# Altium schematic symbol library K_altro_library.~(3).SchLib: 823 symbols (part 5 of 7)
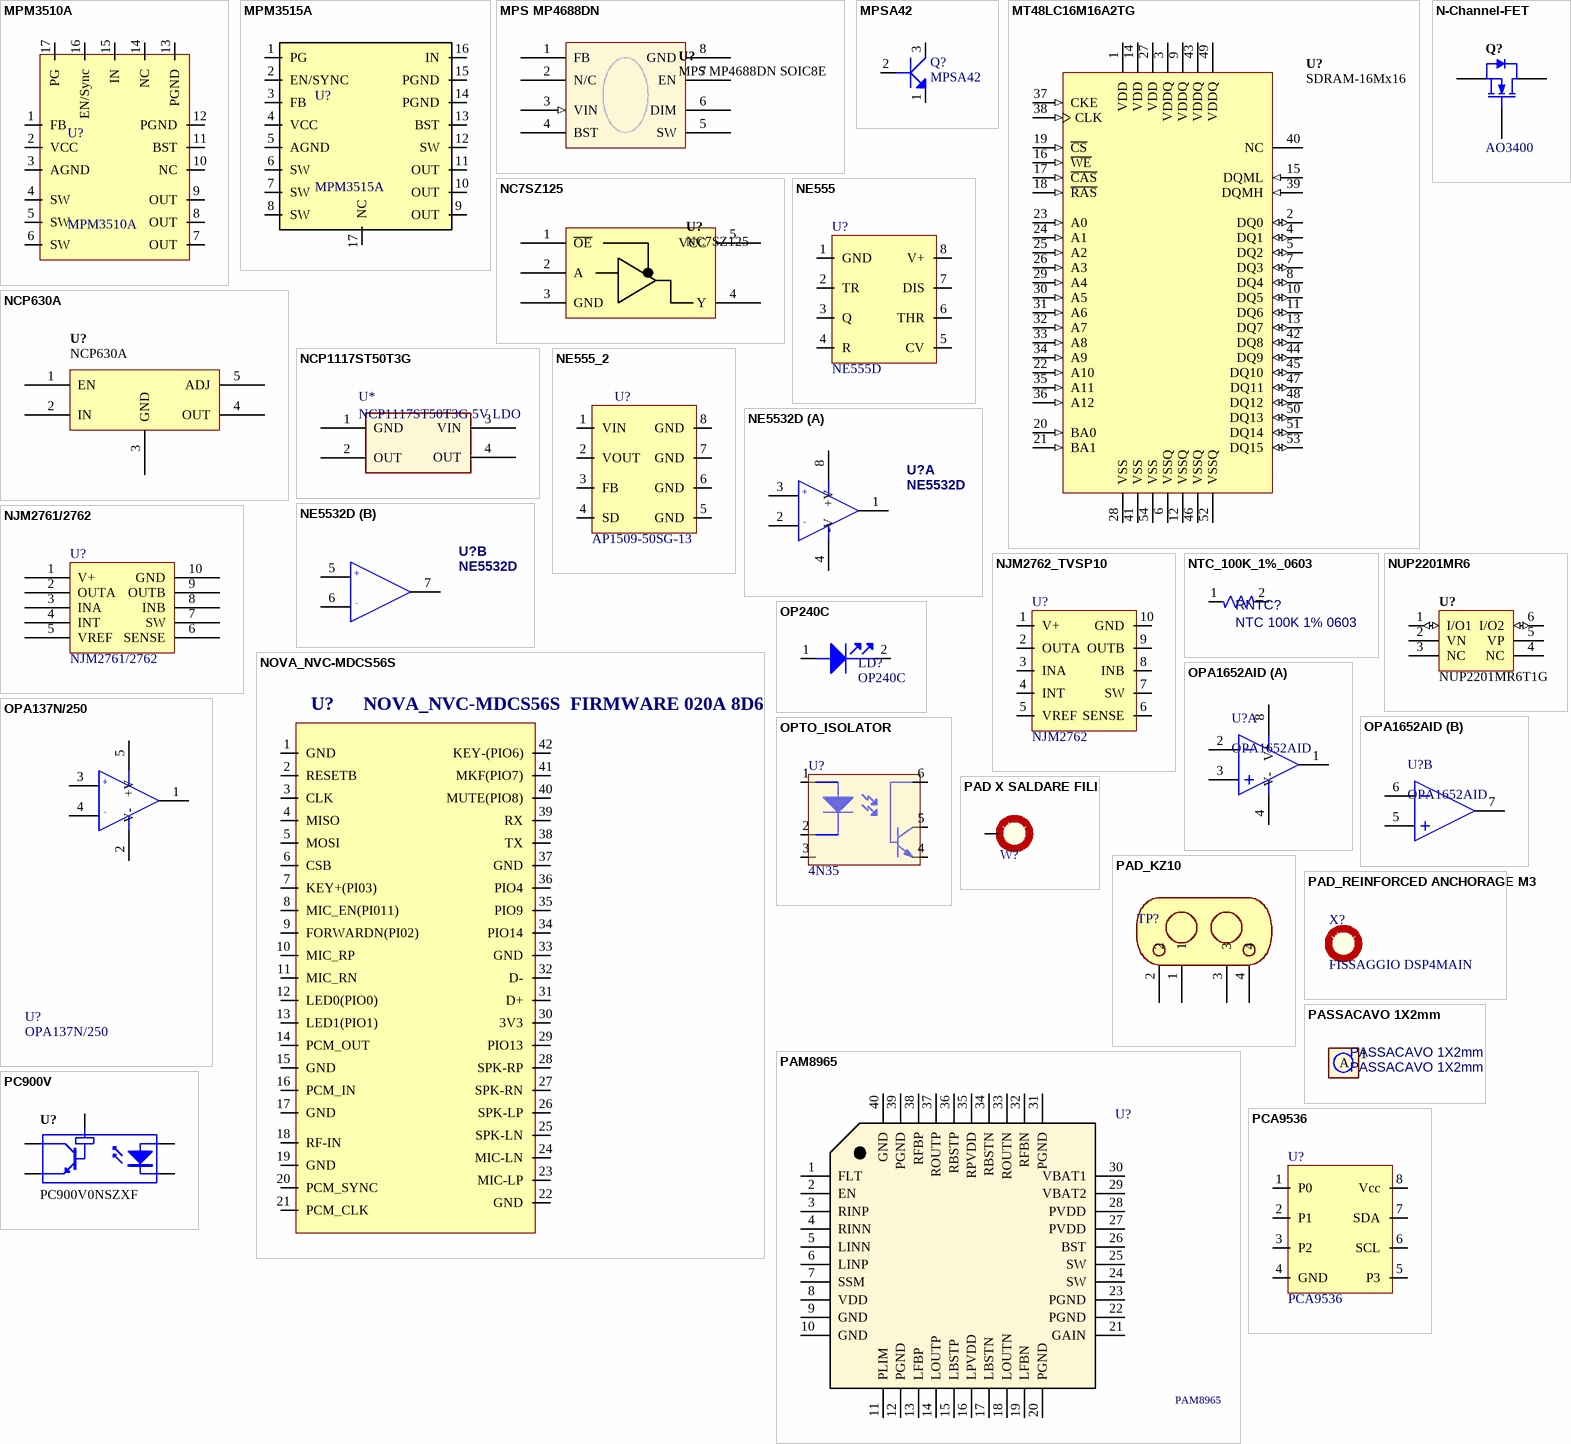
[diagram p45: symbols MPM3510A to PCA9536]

## N-Channel-FET
designator Q?, comment AO3400
N-channel Enhancement Mode Field-effect Transistor;  5.8A/30V; Aggiornato: NO; Costo: 0
footprint SOT95P230-3D
pins: 1 G, 2 D, 3 S

## NC7SZ125
designator U?
Aggiornato: SI; Costo: 0,087; Detail: (RS per >50pz); ContoLavoro: 0
footprint SOT-23 5PIN
pins: 1 ~{OE} "The NCP630 is active when a voltage greater than 2.0V is applied. The NCP630 will be placed into a shutdown mode when a voltage less than 0.8V is applied. If unused then connect the pin high.", 2 A, 3 GND, 4 Y, 5 VCC "Maintans 1.216V between itself and GND"

## NCP630A
designator U?
NCP630A, 3.0A Fast Linear Voltage Regulator, D2PAK; Max Input Voltage: 12 V; Max Output Current: 3 (6.0 peak) A; Max Output Voltage: mV; Aggiornato: NO; Costo: 0
footprint TO-263-2
pins: 1 EN "The NCP630 is active when a voltage greater than 2.0V is applied. The NCP630 will be placed into a shutdown mode when a voltage less than 0.8V is applied. If unused then connect the pin high.", 2 IN, 3 GND, 4 OUT, 5 ADJ "Maintans 1.216V between itself and GND"

## NCP1117ST50T3G
designator U*, comment NCP1117ST50T3G 5V LDO
Detail: prezzo RS; Costo: 0,30; Aggiornato: SI; ContoLavoro: 0
footprint SOT223
pins: 1 GND, 2 OUT, 3 VIN, 4 OUT

## NE555
designator U?, comment NE555D
Costo: 0,24; Aggiornato: NO; ContoLavoro: 0
footprint SO8
pins: 1 GND, 2 TR, 3 Q, 4 R, 5 CV, 6 THR, 7 DIS, 8 V+

## NE555_2
designator U?, comment AP1509-50SG-13
Costo: 1,57; Aggiornato: NO; ContoLavoro: 0
footprint SO8
pins: 1 VIN, 2 VOUT, 3 FB, 4 SD, 5 GND, 6 GND, 7 GND, 8 GND

## NE5532D
designator U?
NE5532D SMD DUAL OP AMP; Costo: 0,10; Aggiornato: SI; ContoLavoro: 0
footprint SO8
footprint SOIC150-8N
part A pins: 1 OUT, 2 -IN, 3 +IN, 4 -V, 8 +V
part B pins: 5 +IN, 6 -IN, 7 OUT

## NJM2761/2762
designator U?
Audio Limiter; Costo: 0; Aggiornato: NO
footprint NJM_TVSP10 (TSSOP, 10-Leads, Body 3x3mm, Pitch 0.5mm, IPC Medium Density)
pins: 1 V+, 2 OUTA, 3 INA, 4 INT, 5 VREF, 6 SENSE, 7 SW, 8 INB, 9 OUTB, 10 GND

## NJM2762_TVSP10
designator U?, comment NJM2762
Hpcode: ICNJM2762RB2; Costo: 0,52; Aggiornato: NO; ContoLavoro: 0
footprint TVSP10
pins: 1 V+, 2 OUTA, 3 INA, 4 INT, 5 VREF, 6 SENSE, 7 SW, 8 INB, 9 OUTB, 10 GND

## NOVA_NVC-MDCS56S
designator U?, comment NOVA_NVC-MDCS56S  FIRMWARE 020A 8D69
Aggiornato: NO; Costo: 0
footprint Bluetooth_NVC-MDCS56S
pins: 1 GND, 2 RESETB, 3 CLK, 4 MISO, 5 MOSI, 6 CSB, 7 KEY+(PI03), 8 MIC_EN(PI011), 9 FORWARDN(PI02), 10 MIC_RP, 11 MIC_RN, 12 LED0(PIO0), 13 LED1(PIO1), 14 PCM_OUT, 15 GND, 16 PCM_IN, 17 GND, 18 RF-IN, 19 GND, 20 PCM_SYNC, 21 PCM_CLK, 22 GND, 23 MIC-LP, 24 MIC-LN, 25 SPK-LN, 26 SPK-LP, 27 SPK-RN, 28 SPK-RP, 29 PIO13, 30 3V3, 31 D+, 32 D-, 33 GND, 34 PIO14, 35 PIO9, 36 PIO4, 37 GND, 38 TX, 39 RX, 40 MUTE(PIO8), 41 MKF(PIO7), 42 KEY-(PIO6)

## NTC_100K_1%_0603
designator RNTC?, comment NTC 100K 1% 0603
Detail: 0,232€ RS >100pz; Costo: 0,232; Aggiornato: S; ContoLavoro: 0
footprint 0603N_RES
pins: 1, 2

## NUP2201MR6
designator U?, comment NUP2201MR6T1G
NUP2201MR6, Low Capacitance Diode Array, USB Protection; Max Input Voltage: mV; Max Output Current: mA; Aggiornato: NO; Costo: 0
footprint TSOP95P275-6
pins: 1 I/O1 (io) "Input/Output 1", 2 VN (power), 3 NC, 4 NC, 5 VP (power), 6 I/O2 (io)

## OP240C
designator LD?
LED IR Optek OP240C; Aggiornato: si; Costo: 0,546; ContoLavoro: 0
footprint OP240C
pins: 1 ANODE, 2 CATHODE

## OPA137N/250
designator U?
Detail: 2,438€ RS >5pz; Aggiornato: s; Costo: 2,438; ContoLavoro: 1
footprint SOT-23 5PIN
pins: 1 OUT, 2 V-, 3 +IN, 4 -IN, 5 +V

## OPA1652AID
designator U?
Sound Plus Low Noise and Distortion, General-Purpose, FET-Input Audio Operational Amplifier, 4.5 to 36 V, -40 to 85 degC, 8-pin SOIC (D8), Green (RoHS & no Sb/Br); Costo: 0,80; ContoLavoro: 0
footprint SOIC150-8N
part A pins: 1 OUT A, 2 IN A-, 3 IN A+, 4 V- (power), 8 V+ (power)
part B pins: 5 IN B+, 6 IN B-, 7 OUT B

## OPTO_ISOLATOR
designator U?, comment 4N35
Aggiornato: NO; Costo: 0
footprint DIP6
pins: 1 ANODE, 2 CATHODE, 3, 4 EMITTER, 5 COLLECTOR, 6 BASE

## PAD X SALDARE FILI
designator W?  (value not drawn)
PAD ANCORAGGIO; Aggiornato: NO; Costo: 0
footprint PAD-DIAM3.05-DR2
footprint PAD-DIAM3.05-DR2
footprint PAD-DIAM2.54-DR1.5
footprint PAD-DIAM2.565-DR2
footprint SMDPAD-RECTANGLE-W3-L8
footprint SMDPAD-ROUND-W3-L7
footprint PAD-W4.1-DR2.4
footprint FIDUCIAL_MARKER-SCHUH (Piazzola per controllo automatico delle saldature SMD (SCHUH))
footprint SIP-1-ETTINGER-13_14_229
footprint PAD-DIAM2-DR1
footprint PAD-DIAM5-DR2.3
footprint PAD-DIAM5.6-DR2.6
footprint PAD-DIAM3-DR1.5
footprint FISS-DIAM6.5-DR3.2
footprint PAD-W3-L5.08-DR1.5
pins: 1

## PAD_KZ10
designator TP?  (no BOM)
Costo: 0; Aggiornato: NO
footprint PAD_KZ10
pins: 1, 2, 3, 4

## PAD_REINFORCED ANCHORAGE M3
designator X?, comment FISSAGGIO DSP4MAIN  (no BOM)
PAD ANCORAGGIO VITE M3; Aggiornato: NO; Costo: 0
footprint FISS-DIAM7.2-DR3.3
footprint FISS-DIAM6.86-DR3.175
footprint FISS-DIAM7.2-DR3.1
footprint FISS-DIAM5.3-DR2.5
footprint FISS-OCT-X6.782-Y6.02-DR3.175
footprint FISS-OCT-X6.782-Y6.02-DR3.5
footprint FISS-DIAM6.5-DR3.1
footprint FISS-DIAM6.83-DR4.7-TSVASM3 (Foro per vite con testa svasata con altezza dal c.s. (dopo fissaggio): 0.5mm)
footprint FISS-DIAM6.5-DR3.2
footprint SCREW_M3_ELECTRIC
pins: 1 (power) hidden to GND

## PAM8965
designator U?
12W STEREO CLASS-D AUDIO AMPLIFIER; MPN: ADAU1701JSTZ; HPcode: da codificare; Detail: 2,50€ Mouser; Costo: 2,50; Aggiornato: NO; ContoLavoro: 0
footprint QFN40_5050 (QFN40_5mmx5mm)
pins: 1 FLT, 2 EN, 3 RINP "Right IN+", 4 RINN "Right IN-", 5 LINN "Left IN-", 6 LINP "Left IN+", 7 SSM, 8 VDD, 9 GND, 10 GND, 11 PLIM, 12 PGND, 13 LFBP, 14 LOUTP "Left OUT+", 15 LBSTP, 16 LPVDD, 17 LBSTN, 18 LOUTN "Left OUT-", 19 LFBN, 20 PGND, 21 GAIN, 22 PGND, 23 PGND, 24 SW, 25 SW, 26 BST, 27 PVDD, 28 PVDD, 29 VBAT2, 30 VBAT1, 31 PGND, 32 RFBN, 33 ROUTN "Right OUT-", 34 RBSTN, 35 RPVDD, 36 RBSTP, 37 ROUTP "Right OUT+", 38 RFBP, 39 PGND, 40 GND

## PASSACAVO 1X2mm
designator PASSACAVO 1X2mm
Costo: 0; Aggiornato: S
footprint PASSACAVO 1X2mm (Footprint not found)
pins: 1 A

## PC900V
designator U?, comment PC900V0NSZXF
OPTOISOLATOR; SMD; Digital Output, Normal OFF  Operation; Aggiornato: NO; Costo: 0
footprint H11L1SR2VM
pins: 1 A "Anode", 2 K "Cathode", 4 Vo "Collector", 5 GND "Emitter", 6 Vcc "Collector"

## PCA9536
designator U?
PCA9536 I2C GPIO EXPANDER; Detail: Da quotare; Costo: 0,99; Aggiornato: NO; ContoLavoro: 0
footprint VSSOP8_DGK_S-PDSO-G
pins: 1 P0, 2 P1, 3 P2, 4 GND, 5 P3, 6 SCL, 7 SDA, 8 Vcc

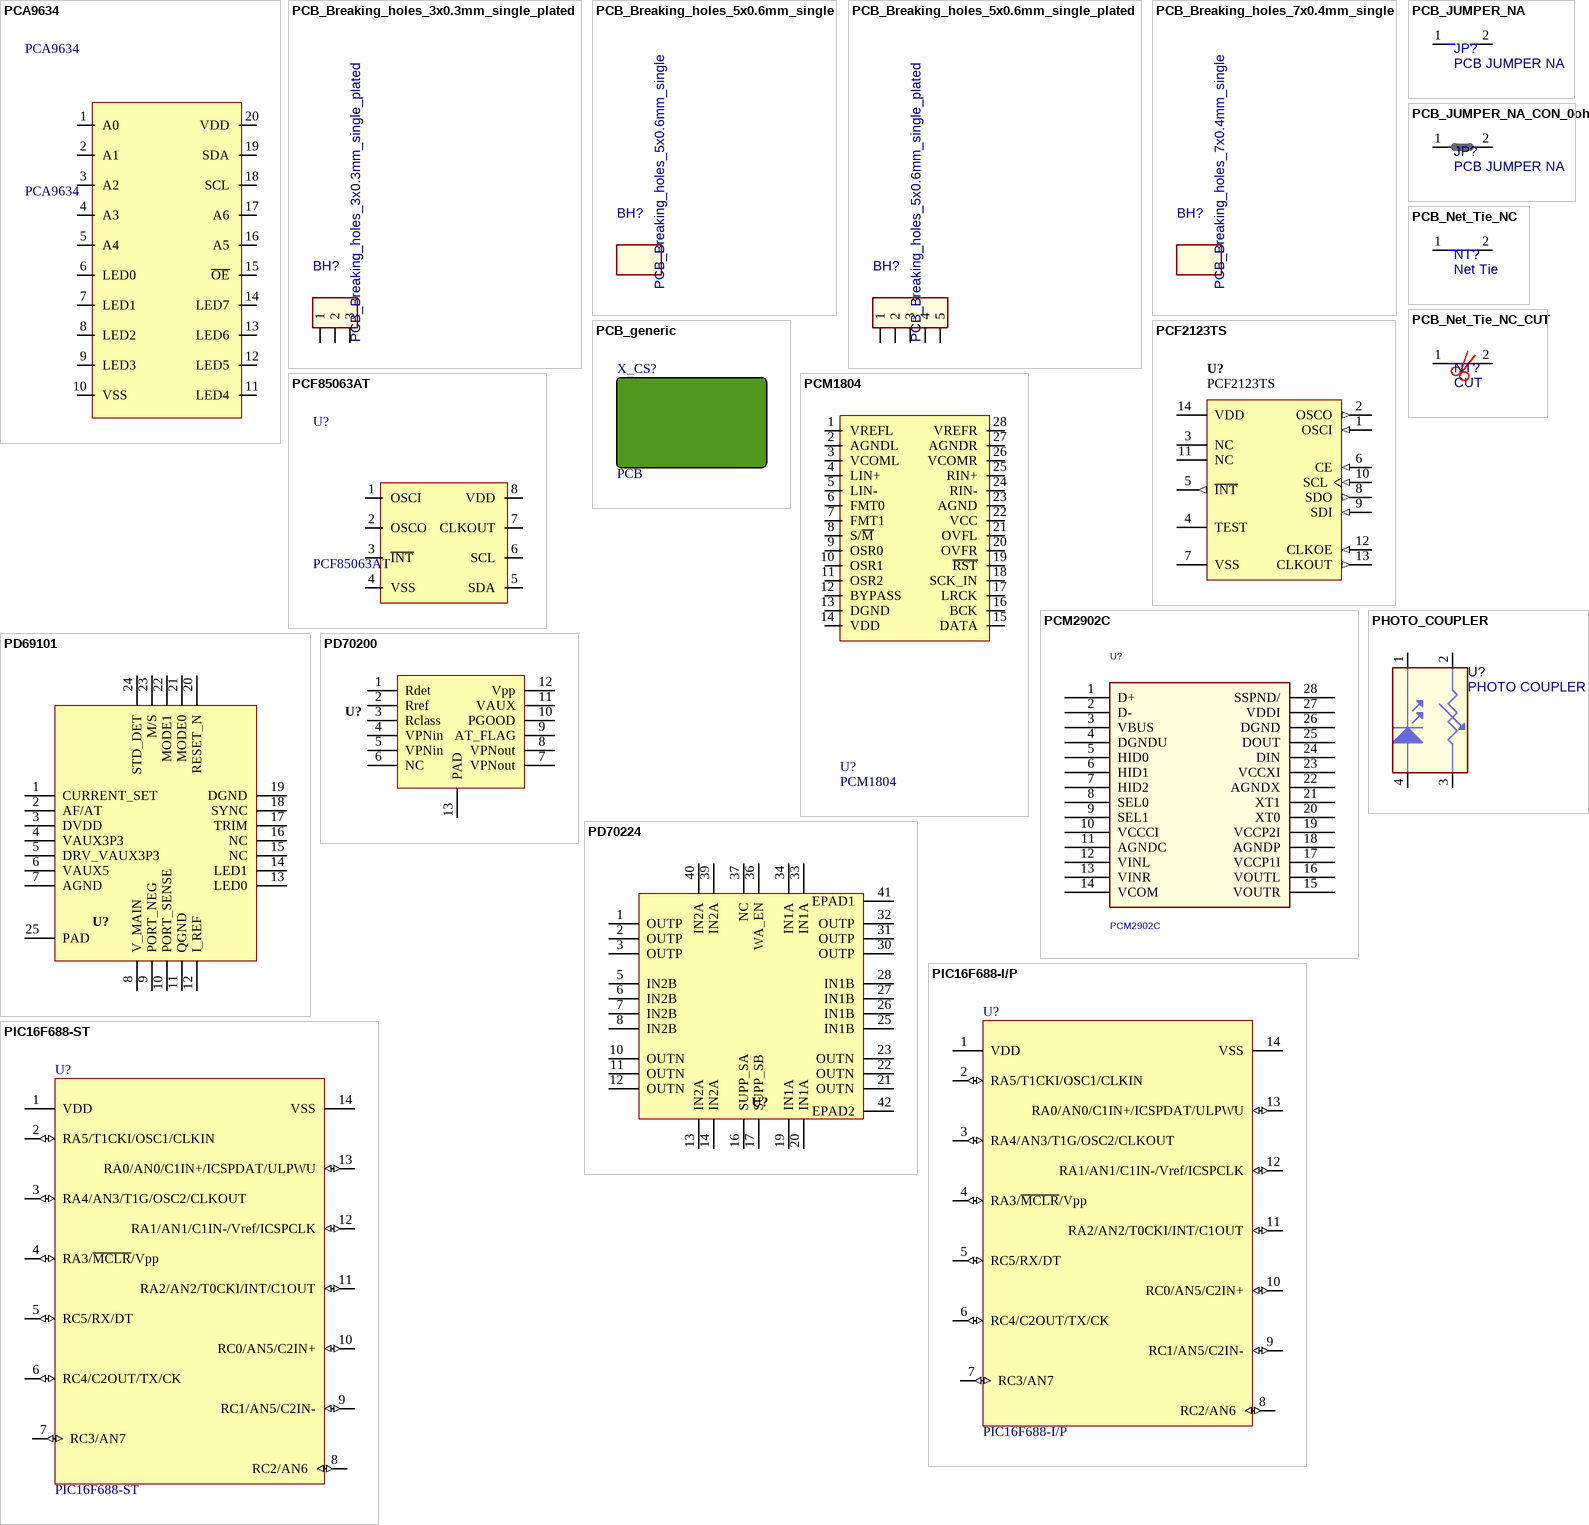
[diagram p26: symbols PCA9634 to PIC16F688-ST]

## PCA9634
designator PCA9634
PCA9634 I2C-bus controlled 8-bit LED driver optimized for / Red/Green/Blue/Amber (RGBA) color mixing applications; Detail: RS 2,28 € pz>75 , TI 1€ pz>1000; Costo: 1; Aggiornato: s; ContoLavoro: 0
footprint SSOP_20
pins: 1 A0, 2 A1, 3 A2, 4 A3, 5 A4, 6 LED0, 7 LED1, 8 LED2, 9 LED3, 10 VSS, 11 LED4, 12 LED5, 13 LED6, 14 LED7, 15 ~{OE}, 16 A5, 17 A6, 18 SCL, 19 SDA, 20 VDD

## PCB_Breaking_holes_3x0.3mm_single_plated
designator BH?  (no BOM)
Aggiornato: S; Costo: 0
footprint PCB_Breaking_holes_3x0.3mm_single_plated (Footprint not found)
pins: 1, 2, 3

## PCB_Breaking_holes_5x0.6mm_single
designator BH?  (no BOM)
Aggiornato: S; Costo: 0
footprint PCB_Breaking_holes_5x0.6mm_single (5 holes 0.6mm breaking holes)

## PCB_Breaking_holes_5x0.6mm_single_plated
designator BH?  (no BOM)
Aggiornato: S; Costo: 0
footprint PCB_Breaking_holes_5x0.6mm_single_plated (Footprint not found)
pins: 1, 2, 3, 4, 5

## PCB_Breaking_holes_7x0.4mm_single
designator BH?  (no BOM)
Aggiornato: S; Costo: 0
footprint Breakaway_tab_7_holes_0.4mm_REFERENCE (7 holes 0.4mm breakaway tab, REFERENCE)

## PCB_generic
designator X_CS?, comment PCB
Costo: 0; ContoLavoro: 1
footprint K_logo_12mmx9mm (LOGO K-array 12mmx9mm)
footprint K_logo_1mmx1mm (LOGO K-array 1mmx1mm)
footprint K_logo_7mmx5mm (LOGO K-array 7mmx5mm)
footprint K_logo_10mmx7mm (LOGO K-array 10mmx7mm)
footprint K_logo_25mmx18mm (LOGO K-array 25mmx18mm)
footprint K_logo_7mmx5mm_overlay (LOGO K-array 7mmx5mm)

## PCB_JUMPER_NA
designator JP?, comment PCB JUMPER NA
PCB_JUMPER_NA; Costo: 0; Value: 0R; Aggiornato: S
simulation model Resistor
footprint 1206_PCB_JUMPER_NA_GOCCIA (1206 PCB JUMPER Normalmente Aperto GOCCIA)
footprint PCB_JUMPER_NA_GOCCIA (PCB JUMPER Normalmente Aperto GOCCIA)
footprint D2mm_PCB_JUMPER_NA_GOCCIA (D2mm PCB JUMPER Normalmente Aperto GOCCIA)
footprint 0402N_RES_PCB_JUMPER_NA_GOCCIA (0402N_RES PCB JUMPER Normalmente Aperto GOCCIA)
footprint 0805_UP_PCB_JUMPER_NA_GOCCIA (0805 PCB JUMPER Normalmente Aperto GOCCIA)
footprint 0805_UP_RES_NO3D
pins: 1, 2

## PCB_JUMPER_NA_CON_0ohm
designator JP?, comment PCB JUMPER NA
PCB_JUMPER_NA con 0ohm; Costo: 0; Value: 0R; Aggiornato: S
simulation model Resistor
footprint 1206_PCB_JUMPER_NA_GOCCIA+R_1206 (1206 PCB JUMPER Normalmente Aperto GOCCIA + R 1206)
footprint PCB_JUMPER_NA_GOCCIA (PCB JUMPER Normalmente Aperto GOCCIA)
footprint D2mm_PCB_JUMPER_NA_GOCCIA (D2mm PCB JUMPER Normalmente Aperto GOCCIA)
footprint 0402N_RES_PCB_JUMPER_NA_GOCCIA (0402N_RES PCB JUMPER Normalmente Aperto GOCCIA)
footprint 0805_UP_PCB_JUMPER_NA_GOCCIA+R_0805 (0805 PCB JUMPER Normalmente Aperto GOCCIA + R 0805)
pins: 1, 2

## PCB_Net_Tie_NC
designator NT?, comment Net Tie  (net tie, no BOM)
Costo: 0; Value: 0R; Aggiornato: S
simulation model Resistor
footprint 1206_UP_PCB_JUMPER
footprint 1812_UP_PCB_JUMPER
footprint 1206_PCB_JUMPER_NC_GOCCIA (1206 PCB JUMPER Normalmente Chiuso GOCCIA)
footprint DO214AC_21_PCB_JUMPER
footprint 2512_PCB_JUMPER
footprint 1210_UP_PCB_JUMPER
footprint 0805_UP_PCB_JUMPER
footprint 0603_UP_PCB_JUMPER
footprint 0603N_RES_PCB_JUMPER
footprint 0402N_RES_PCB_JUMPER_NC_GOCCIA (0402N_RES PCB JUMPER Normalmente chiuso GOCCIA)
footprint D2mm_PCB_JUMPER_NC_GOCCIA (D2mm PCB JUMPER Normalmente Chiuso GOCCIA)
footprint PCB_JUMPER_NC_GOCCIA (PCB JUMPER Normalmente Chiuso GOCCIA)
footprint 0402N_RES_PCB_JUMPER
footprint 0402_K_PCB_JUMPER (0402 K-array leggermente ridotto rispetto a EIA)
footprint 0805_UP_PCB_JUMPER _0.9mm
pins: 1, 2

## PCB_Net_Tie_NC_CUT
designator NT?, comment CUT
CUT the Net Tie; Costo: 0; Value: 0R; Aggiornato: S
simulation model Resistor
footprint 1206_UP_PCB_JUMPER
footprint 1812_UP_PCB_JUMPER
footprint 1206_PCB_JUMPER_NC_GOCCIA (1206 PCB JUMPER Normalmente Chiuso GOCCIA)
footprint DO214AC_21_PCB_JUMPER
footprint 2512_PCB_JUMPER
footprint 1210_UP_PCB_JUMPER
footprint 0805_UP_PCB_JUMPER
footprint 0603_UP_PCB_JUMPER
footprint 0603N_RES_PCB_JUMPER
footprint 0402N_RES_PCB_JUMPER_NC_GOCCIA (0402N_RES PCB JUMPER Normalmente chiuso GOCCIA)
footprint D2mm_PCB_JUMPER_NC_GOCCIA (D2mm PCB JUMPER Normalmente Chiuso GOCCIA)
footprint PCB_JUMPER_NC_GOCCIA (PCB JUMPER Normalmente Chiuso GOCCIA)
footprint 0402N_RES_PCB_JUMPER
footprint 0402_K_PCB_JUMPER (0402 K-array leggermente ridotto rispetto a EIA)
footprint 0805_UP_PCB_JUMPER _0.9mm
pins: 1, 2

## PCF2123TS
designator U?
PCF2123TS, SPI Real time clock/calendar, TSSOP14; Nominal Fequency: 32.768 KHz; Aggiornato: NO; Costo: 0
footprint TSOP65P640-14AN
pins: 1 OSCI (in), 2 OSCO (out), 3 NC, 4 TEST, 5 ~{INT} (out), 6 CE (in), 7 VSS (power), 8 SDO (out), 9 SDI (in), 10 SCL (in), 11 NC, 12 CLKOE (in), 13 CLKOUT (out), 14 VDD (power)

## PCF85063AT
designator U?
PCF85063AT RTC I2C; Costo: 0,5; Aggiornato: s; ContoLavoro: 0
footprint SO8
pins: 1 OSCI, 2 OSCO, 3 ~{INT}, 4 VSS, 5 SDA, 6 SCL, 7 CLKOUT, 8 VDD

## PCM1804
designator U?
PCM1804 24Bit 192kHz adc SIGMADELTA; MPN: PCM1804DB; Aggiornato: S; Costo: 3; ContoLavoro: 1
footprint VSOP28
pins: 1 VREFL, 2 AGNDL, 3 VCOML, 4 LIN+, 5 LIN-, 6 FMT0, 7 FMT1, 8 S/~{M}, 9 OSR0, 10 OSR1, 11 OSR2, 12 BYPASS, 13 DGND, 14 VDD, 15 DATA "DATA/DSDR", 16 BCK "BCK/DSDL", 17 LRCK "LRCK/DSDBCK", 18 SCK_IN, 19 ~{RST}, 20 OVFR, 21 OVFL, 22 VCC, 23 AGND, 24 RIN-, 25 RIN+, 26 VCOMR, 27 AGNDR, 28 VREFR

## PCM2902C
designator U?
Aggiornato: SI; Costo: 7,5; ContoLavoro: 0
footprint SSOP_28
pins: 1 D+, 2 D-, 3 VBUS, 4 DGNDU, 5 HID0, 6 HID1, 7 HID2, 8 SEL0, 9 SEL1, 10 VCCCI, 11 AGNDC, 12 VINL, 13 VINR, 14 VCOM, 15 VOUTR, 16 VOUTL, 17 VCCP1I, 18 AGNDP, 19 VCCP2I, 20 XT0, 21 XT1, 22 AGNDX, 23 VCCXI, 24 DIN, 25 DOUT, 26 DGND, 27 VDDI, 28 SSPND/

## PD69101
designator U?  (value not drawn)
PD69101 Microsemi 1 Port PSE PoE PD69101 Controller; Aggiornato: si; Costo: 2,2; HPcode: ICPD69101; ContoLavoro: 1
footprint PD69101
footprint PD69101_MOD_PAD (PD69101 ISOLAMENTO PAD AUMENTATO)
pins: 1 CURRENT_SET, 2 AF/AT, 3 DVDD, 4 VAUX3P3, 5 DRV_VAUX3P3, 6 VAUX5, 7 AGND, 8 V_MAIN, 9 PORT_NEG, 10 PORT_SENSE, 11 QGND, 12 I_REF, 13 LED0, 14 LED1, 15 NC, 16 NC, 17 TRIM, 18 SYNC, 19 DGND, 20 RESET_N, 21 MODE0, 22 MODE1, 23 M/S, 24 STD_DET, 25 PAD

## PD70200
designator U?  (value not drawn)
PD70200 Microsemi IEEE 802.3af/at PD Front End IC; Aggiornato: si; Costo: 1,05; HPcode: ICPD70200; ContoLavoro: 1
footprint PD70200 (Footprint not found)
footprint PD70200_MOD_PAD (PD702200 ISOLAMENTO PAD AUMENTATO)
pins: 1 Rdet, 2 Rref, 3 Rclass, 4 VPNin, 5 VPNin, 6 NC, 7 VPNout, 8 VPNout, 9 AT_FLAG, 10 PGOOD, 11 VAUX, 12 Vpp, 13 PAD

## PD70224
designator U?  (value not drawn)
PD70224 Microsemi Dual MOSFET-based Bridge Rectifier; Aggiornato: si; Costo: 2,2; HPcode: ICPD70224; ContoLavoro: 1
footprint PD70224
footprint PD70224_MOD_PAD (PD70224 ISOLAMENTO PAD AUMENTATO)
pins: 1 OUTP, 2 OUTP, 3 OUTP, 5 IN2B, 6 IN2B, 7 IN2B, 8 IN2B, 10 OUTN, 11 OUTN, 12 OUTN, 13 IN2A, 14 IN2A, 16 SUPP_SA, 17 SUPP_SB, 19 IN1A, 20 IN1A, 21 OUTN, 22 OUTN, 23 OUTN, 25 IN1B, 26 IN1B, 27 IN1B, 28 IN1B, 30 OUTP, 31 OUTP, 32 OUTP, 33 IN1A, 34 IN1A, 36 WA_EN, 37 NC, 39 IN2A, 40 IN2A, 41 EPAD1, 42 EPAD2

## PHOTO_COUPLER
designator U?, comment PHOTO COUPLER
Hpcode: RESPHOTO; Costo: 0,8; Aggiornato: S; ContoLavoro: 0
footprint PHOTO_COUPLER_3MM
footprint PHOTO_COUPLER_3MM_ALT_SERIG
simulation model PHOTO_COUPLER_beta
pins: 1 CAT, 2 R1, 3 R2, 4 ANODE

## PIC16F688-I/P
designator U?
Aggiornato: NO; Costo: 1,39; ContoLavoro: 0
footprint DIP.100/14/W.300/L.800
pins: 1 VDD (power), 2 RA5/T1CKI/OSC1/CLKIN (io), 3 RA4/AN3/T1G/OSC2/CLKOUT (io), 4 RA3/~{MCLR}/Vpp (io), 5 RC5/RX/DT (io), 6 RC4/C2OUT/TX/CK (io), 7 RC3/AN7 (io), 8 RC2/AN6 (io), 9 RC1/AN5/C2IN- (io), 10 RC0/AN5/C2IN+ (io), 11 RA2/AN2/T0CKI/INT/C1OUT (io), 12 RA1/AN1/C1IN-/Vref/ICSPCLK (io), 13 RA0/AN0/C1IN+/ICSPDAT/ULPWU (io), 14 VSS (power)

## PIC16F688-ST
designator U?
Aggiornato: NO; Costo: 1,44; ContoLavoro: 0
footprint TSSOP14
pins: 1 VDD (power), 2 RA5/T1CKI/OSC1/CLKIN (io), 3 RA4/AN3/T1G/OSC2/CLKOUT (io), 4 RA3/~{MCLR}/Vpp (io), 5 RC5/RX/DT (io), 6 RC4/C2OUT/TX/CK (io), 7 RC3/AN7 (io), 8 RC2/AN6 (io), 9 RC1/AN5/C2IN- (io), 10 RC0/AN5/C2IN+ (io), 11 RA2/AN2/T0CKI/INT/C1OUT (io), 12 RA1/AN1/C1IN-/Vref/ICSPCLK (io), 13 RA0/AN0/C1IN+/ICSPDAT/ULPWU (io), 14 VSS (power)

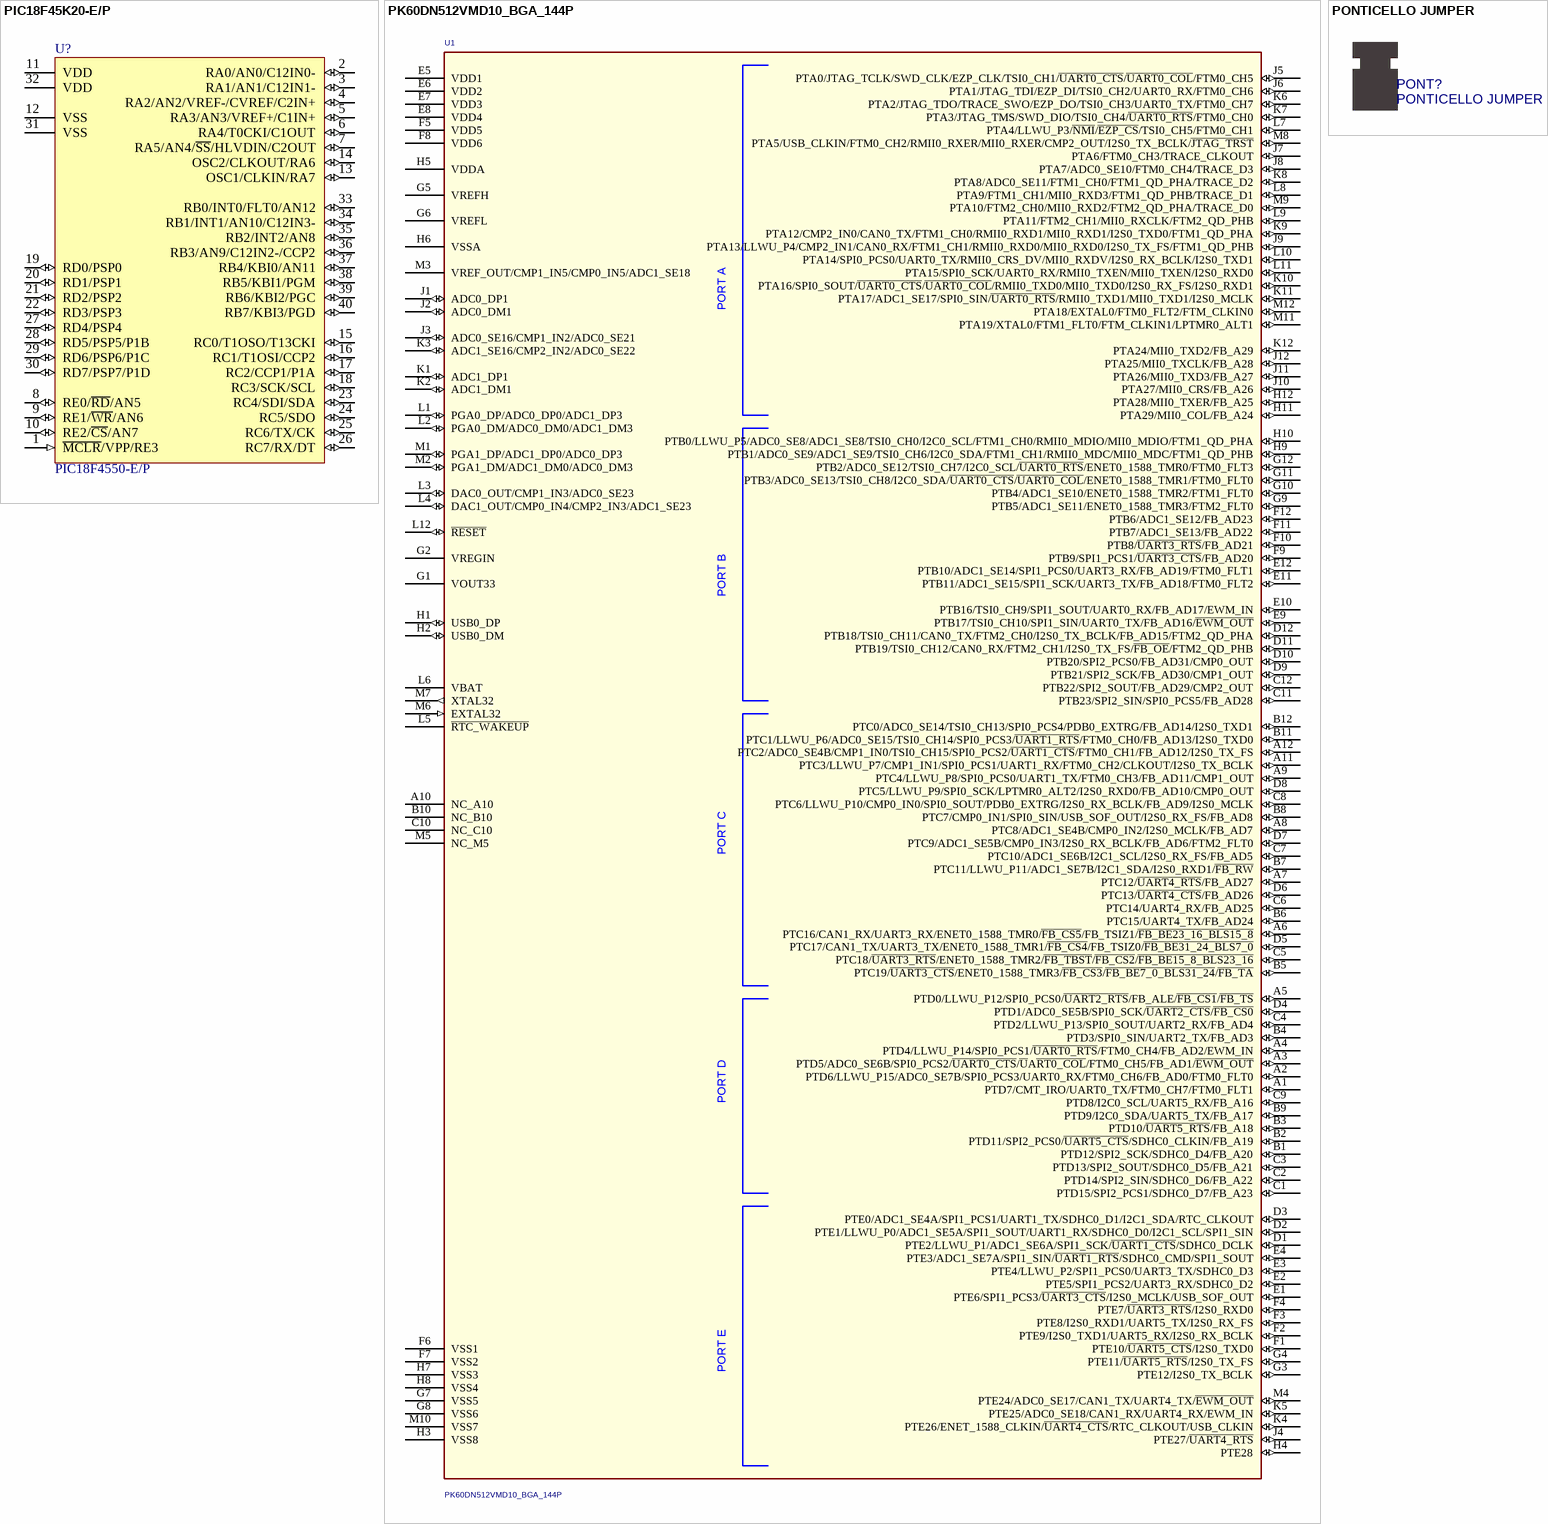
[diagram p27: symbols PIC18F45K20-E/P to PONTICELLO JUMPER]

## PIC18F45K20-E/P
designator U?, comment PIC18F4550-E/P
Flash Microcontroller with 10-Bit A/D and nanoWatt Technology, 32K Flash, 40-Pin PDIP, Extended Temperature Range; Aggiornato: NO; Costo: 0
footprint PDIP600-P40 (DIP, 40-Leads, Row Spacing 15.24mm, Pitch 2.54mm, Body 51.8x13.5mm)
pins: 1 ~{MCLR}/VPP/RE3 (in), 2 RA0/AN0/C12IN0- (io), 3 RA1/AN1/C12IN1- (io), 4 RA2/AN2/VREF-/CVREF/C2IN+ (io), 5 RA3/AN3/VREF+/C1IN+ (io), 6 RA4/T0CKI/C1OUT (io), 7 RA5/AN4/~{SS}/HLVDIN/C2OUT (io), 8 RE0/~{RD}/AN5 (io), 9 RE1/~{WR}/AN6 (io), 10 RE2/~{CS}/AN7 (io), 11 VDD (power), 12 VSS (power), 13 OSC1/CLKIN/RA7 (io), 14 OSC2/CLKOUT/RA6 (io), 15 RC0/T1OSO/T13CKI (io), 16 RC1/T1OSI/CCP2 (io), 17 RC2/CCP1/P1A (io), 18 RC3/SCK/SCL (io), 19 RD0/PSP0 (io), 20 RD1/PSP1 (io), 21 RD2/PSP2 (io), 22 RD3/PSP3 (io), 23 RC4/SDI/SDA (io), 24 RC5/SDO (io), 25 RC6/TX/CK (io), 26 RC7/RX/DT (io), 27 RD4/PSP4 (io), 28 RD5/PSP5/P1B (io), 29 RD6/PSP6/P1C (io), 30 RD7/PSP7/P1D (io), 31 VSS (power), 32 VDD (power), 33 RB0/INT0/FLT0/AN12 (io), 34 RB1/INT1/AN10/C12IN3- (io), 35 RB2/INT2/AN8 (io), 36 RB3/AN9/C12IN2-/CCP2 (io), 37 RB4/KBI0/AN11 (io), 38 RB5/KBI1/PGM (io), 39 RB6/KBI2/PGC (io), 40 RB7/KBI3/PGD (io)

## PK60DN512VMD10_BGA_144P
designator U1
Costo: 0; Aggiornato: NO
pins: A1 PTD7/CMT_IRO/UART0_TX/FTM0_CH7/FTM0_FLT1 (io), A2 PTD6/LLWU_P15/ADC0_SE7B/SPI0_PCS3/UART0_RX/FTM0_CH6/FB_AD0/FTM0_FLT0 (io), A3 PTD5/ADC0_SE6B/SPI0_PCS2/~{UART0_CTS}/~{U}A~{RT0_COL}/FTM0_CH5/FB_AD1/~{EWM_OUT} (io), A4 PTD4/LLWU_P14/SPI0_PCS1/~{UART0_RTS}/FTM0_CH4/FB_AD2/EWM_IN (io), A5 PTD0/LLWU_P12/SPI0_PCS0/~{UART2_RTS}/FB_ALE/~{FB_CS1}/~{FB_TS} (io), A6 PTC16/CAN1_RX/UART3_RX/ENET0_1588_TMR0/~{FB_CS5}/FB_TSIZ1/~{FB_BE23_16_BLS15_8} (io), A7 PTC12/~{UART4_RTS}/FB_AD27 (io), A8 PTC8/ADC1_SE4B/CMP0_IN2/I2S0_MCLK/FB_AD7 (io), A9 PTC4/LLWU_P8/SPI0_PCS0/UART1_TX/FTM0_CH3/FB_AD11/CMP1_OUT (io), A10 NC_A10, A11 PTC3/LLWU_P7/CMP1_IN1/SPI0_PCS1/UART1_RX/FTM0_CH2/CLKOUT/I2S0_TX_BCLK (io), A12 PTC2/ADC0_SE4B/CMP1_IN0/TSI0_CH15/SPI0_PCS2/~{UART1_CTS}/FTM0_CH1/FB_AD12/I2S0_TX_FS (io), B1 PTD12/SPI2_SCK/SDHC0_D4/FB_A20 (io), B2 PTD11/SPI2_PCS0/~{UART5_CTS}/SDHC0_CLKIN/FB_A19 (io), B3 PTD10/~{UART5_RTS}/FB_A18 (io), B4 PTD3/SPI0_SIN/UART2_TX/FB_AD3 (io), B5 PTC19/~{UART3_CTS}/ENET0_1588_TMR3/~{FB_CS3}/~{FB_BE7_0_BLS31_24}/~{FB_TA} (io), B6 PTC15/UART4_TX/FB_AD24 (io), B7 PTC11/LLWU_P11/ADC1_SE7B/I2C1_SDA/I2S0_RXD1/~{FB_RW} (io), B8 PTC7/CMP0_IN1/SPI0_SIN/USB_SOF_OUT/I2S0_RX_FS/FB_AD8 (io), B9 PTD9/I2C0_SDA/UART5_TX/FB_A17 (io), B10 NC_B10, B11 PTC1/LLWU_P6/ADC0_SE15/TSI0_CH14/SPI0_PCS3/~{UART1_RTS}/FTM0_CH0/FB_AD13/I2S0_TXD0 (io), B12 PTC0/ADC0_SE14/TSI0_CH13/SPI0_PCS4/PDB0_EXTRG/FB_AD14/I2S0_TXD1 (io), C1 PTD15/SPI2_PCS1/SDHC0_D7/FB_A23 (io), C2 PTD14/SPI2_SIN/SDHC0_D6/FB_A22 (io), C3 PTD13/SPI2_SOUT/SDHC0_D5/FB_A21 (io), C4 PTD2/LLWU_P13/SPI0_SOUT/UART2_RX/FB_AD4 (io), C5 PTC18/~{UART3_RTS}/ENET0_1588_TMR2/~{FB_TBST}/~{FB_CS2}/~{FB_BE15_8_BLS23_16} (io), C6 PTC14/UART4_RX/FB_AD25 (io), C7 PTC10/ADC1_SE6B/I2C1_SCL/I2S0_RX_FS/FB_AD5 (io), C8 PTC6/LLWU_P10/CMP0_IN0/SPI0_SOUT/PDB0_EXTRG/I2S0_RX_BCLK/FB_AD9/I2S0_MCLK (io), C9 PTD8/I2C0_SCL/UART5_RX/FB_A16 (io), C10 NC_C10, C11 PTB23/SPI2_SIN/SPI0_PCS5/FB_AD28 (io), C12 PTB22/SPI2_SOUT/FB_AD29/CMP2_OUT (io), D1 PTE2/LLWU_P1/ADC1_SE6A/SPI1_SCK/~{UART1_CTS}/SDHC0_DCLK (io), D2 PTE1/LLWU_P0/ADC1_SE5A/SPI1_SOUT/UART1_RX/SDHC0_D0/I2C1_SCL/SPI1_SIN (io), D3 PTE0/ADC1_SE4A/SPI1_PCS1/UART1_TX/SDHC0_D1/I2C1_SDA/RTC_CLKOUT (io), D4 PTD1/ADC0_SE5B/SPI0_SCK/~{UART2_CTS}/~{FB_CS0} (io), D5 PTC17/CAN1_TX/UART3_TX/ENET0_1588_TMR1/~{FB_CS4}/FB_TSIZ0/~{FB_BE31_24_BLS7_0} (io), D6 PTC13/~{UART4_CTS}/FB_AD26 (io), D7 PTC9/ADC1_SE5B/CMP0_IN3/I2S0_RX_BCLK/FB_AD6/FTM2_FLT0 (io), D8 PTC5/LLWU_P9/SPI0_SCK/LPTMR0_ALT2/I2S0_RXD0/FB_AD10/CMP0_OUT (io), D9 PTB21/SPI2_SCK/FB_AD30/CMP1_OUT (io), D10 PTB20/SPI2_PCS0/FB_AD31/CMP0_OUT (io), D11 PTB19/TSI0_CH12/CAN0_RX/FTM2_CH1/I2S0_TX_FS/~{FB_OE}/FTM2_QD_PHB (io), D12 PTB18/TSI0_CH11/CAN0_TX/FTM2_CH0/I2S0_TX_BCLK/FB_AD15/FTM2_QD_PHA (io), E1 PTE6/SPI1_PCS3/~{UART3_CTS}/I2S0_MCLK/USB_SOF_OUT (io), E2 PTE5/SPI1_PCS2/UART3_RX/SDHC0_D2 (io), E3 PTE4/LLWU_P2/SPI1_PCS0/UART3_TX/SDHC0_D3 (io), E4 PTE3/ADC1_SE7A/SPI1_SIN/~{UART1_RTS}/SDHC0_CMD/SPI1_SOUT (io), E5 VDD1 (power), E6 VDD2 (power), E7 VDD3 (power), E8 VDD4 (power), E9 PTB17/TSI0_CH10/SPI1_SIN/UART0_TX/FB_AD16/~{EWM_OUT} (io), E10 PTB16/TSI0_CH9/SPI1_SOUT/UART0_RX/FB_AD17/EWM_IN (io), E11 PTB11/ADC1_SE15/SPI1_SCK/UART3_TX/FB_AD18/FTM0_FLT2 (io), E12 PTB10/ADC1_SE14/SPI1_PCS0/UART3_RX/FB_AD19/FTM0_FLT1 (io), F1 PTE10/~{UART5_CTS}/I2S0_TXD0 (io), F2 PTE9/I2S0_TXD1/UART5_RX/I2S0_RX_BCLK (io), F3 PTE8/I2S0_RXD1/UART5_TX/I2S0_RX_FS (io), F4 PTE7/~{UART3_RTS}/I2S0_RXD0 (io), F5 VDD5 (power), F6 VSS1 (power), F7 VSS2 (power), F8 VDD6 (power), F9 PTB9/SPI1_PCS1/~{UART3_CTS}/FB_AD20 (io), F10 PTB8/~{UART3_RTS}/FB_AD21 (io), F11 PTB7/ADC1_SE13/FB_AD22 (io), F12 PTB6/ADC1_SE12/FB_AD23 (io), G1 VOUT33 (power), G2 VREGIN (power), G3 PTE12/I2S0_TX_BCLK (io), G4 PTE11/~{UART5_RTS}/I2S0_TX_FS (io), G5 VREFH (power), G6 VREFL (power), G7 VSS5 (power), G8 VSS6 (power), G9 PTB5/ADC1_SE11/ENET0_1588_TMR3/FTM2_FLT0 (io), G10 PTB4/ADC1_SE10/ENET0_1588_TMR2/FTM1_FLT0 (io), G11 PTB3/ADC0_SE13/TSI0_CH8/I2C0_SDA/~{UART0_CTS}/~{UART0_COL}/ENET0_1588_TMR1/FTM0_FLT0 (io), G12 PTB2/ADC0_SE12/TSI0_CH7/I2C0_SCL/~{UART0_RTS}/ENET0_1588_TMR0/FTM0_FLT3 (io), H1 USB0_DP (io), H2 USB0_DM (io), H3 VSS8 (power), H4 PTE28 (io), H5 VDDA (power), H6 VSSA (power), H7 VSS3 (power), H8 VSS4 (power), H9 PTB1/ADC0_SE9/ADC1_SE9/TSI0_CH6/I2C0_SDA/FTM1_CH1/RMII0_MDC/MII0_MDC/FTM1_QD_PHB (io), H10 PTB0/LLWU_P5/ADC0_SE8/ADC1_SE8/TSI0_CH0/I2C0_SCL/FTM1_CH0/RMII0_MDIO/MII0_MDIO/FTM1_QD_PHA (io), H11 PTA29/MII0_COL/FB_A24 (io), H12 PTA28/MII0_TXER/FB_A25 (io), J1 ADC0_DP1 (io), J2 ADC0_DM1 (io), J3 ADC0_SE16/CMP1_IN2/ADC0_SE21 (io), J4 PTE27/~{UART4_RTS} (io), J5 PTA0/JTAG_TCLK/SWD_CLK/EZP_CLK/TSI0_CH1/~{UART0_CTS}/~{UART0_COL}/FTM0_CH5 (io), J6 PTA1/JTAG_TDI/EZP_DI/TSI0_CH2/UART0_RX/FTM0_CH6 (io), J7 PTA6/FTM0_CH3/TRACE_CLKOUT (io), J8 PTA7/ADC0_SE10/FTM0_CH4/TRACE_D3 (io), J9 PTA13/LLWU_P4/CMP2_IN1/CAN0_RX/FTM1_CH1/RMII0_RXD0/MII0_RXD0/I2S0_TX_FS/FTM1_QD_PHB (io), J10 PTA27/MII0_CRS/FB_A26 (io), J11 PTA26/MII0_TXD3/FB_A27 (io), J12 PTA25/MII0_TXCLK/FB_A28 (io), K1 ADC1_DP1 (io), K2 ADC1_DM1 (io), K3 ADC1_SE16/CMP2_IN2/ADC0_SE22 (io), K4 PTE26/ENET_1588_CLKIN/~{UART4_CTS}/RTC_CLKOUT/USB_CLKIN (io), K5 PTE25/ADC0_SE18/CAN1_RX/UART4_RX/EWM_IN (io), K6 PTA2/JTAG_TDO/TRACE_SWO/EZP_DO/TSI0_CH3/UART0_TX/FTM0_CH7 (io), K7 PTA3/JTAG_TMS/SWD_DIO/TSI0_CH4/~{UART0_RTS}/FTM0_CH0 (io), K8 PTA8/ADC0_SE11/FTM1_CH0/FTM1_QD_PHA/TRACE_D2 (io), K9 PTA12/CMP2_IN0/CAN0_TX/FTM1_CH0/RMII0_RXD1/MII0_RXD1/I2S0_TXD0/FTM1_QD_PHA (io), K10 PTA16/SPI0_SOUT/~{UART0_CTS}/~{UART0_COL}/RMII0_TXD0/MII0_TXD0/I2S0_RX_FS/I2S0_RXD1 (io), K11 PTA17/ADC1_SE17/SPI0_SIN/~{UART0_RTS}/RMII0_TXD1/MII0_TXD1/I2S0_MCLK (io), K12 PTA24/MII0_TXD2/FB_A29 (io), L1 PGA0_DP/ADC0_DP0/ADC1_DP3 (io), L2 PGA0_DM/ADC0_DM0/ADC1_DM3 (io), L3 DAC0_OUT/CMP1_IN3/ADC0_SE23 (io), L4 DAC1_OUT/CMP0_IN4/CMP2_IN3/ADC1_SE23 (io), L5 ~{RTC_WAKEUP}, L6 VBAT (power), L7 PTA4/LLWU_P3/~{NMI}/~{EZP_CS}/TSI0_CH5/FTM0_CH1 (io), L8 PTA9/FTM1_CH1/MII0_RXD3/FTM1_QD_PHB/TRACE_D1 (io), L9 PTA11/FTM2_CH1/MII0_RXCLK/FTM2_QD_PHB (io), L10 PTA14/SPI0_PCS0/UART0_TX/RMII0_CRS_DV/MII0_RXDV/I2S0_RX_BCLK/I2S0_TXD1 (io), L11 PTA15/SPI0_SCK/UART0_RX/RMII0_TXEN/MII0_TXEN/I2S0_RXD0 (io), L12 ~{RESET} (io), M1 PGA1_DP/ADC1_DP0/ADC0_DP3 (io), M2 PGA1_DM/ADC1_DM0/ADC0_DM3 (io), M3 VREF_OUT/CMP1_IN5/CMP0_IN5/ADC1_SE18 (power), M4 PTE24/ADC0_SE17/CAN1_TX/UART4_TX/~{EWM_OUT} (io), M5 NC_M5, M6 EXTAL32 (in), M7 XTAL32 (out), M8 PTA5/USB_CLKIN/FTM0_CH2/RMII0_RXER/MII0_RXER/CMP2_OUT/I2S0_TX_BCLK/~{JTAG_TRST} (io), M9 PTA10/FTM2_CH0/MII0_RXD2/FTM2_QD_PHA/TRACE_D0 (io), M10 VSS7 (power), M11 PTA19/XTAL0/FTM1_FLT0/FTM_CLKIN1/LPTMR0_ALT1 (io), M12 PTA18/EXTAL0/FTM0_FLT2/FTM_CLKIN0 (io)

## PONTICELLO JUMPER
designator PONT?
Detail: (RS per >1000pz); Costo: 0,025; Aggiornato: S; ContoLavoro: 0

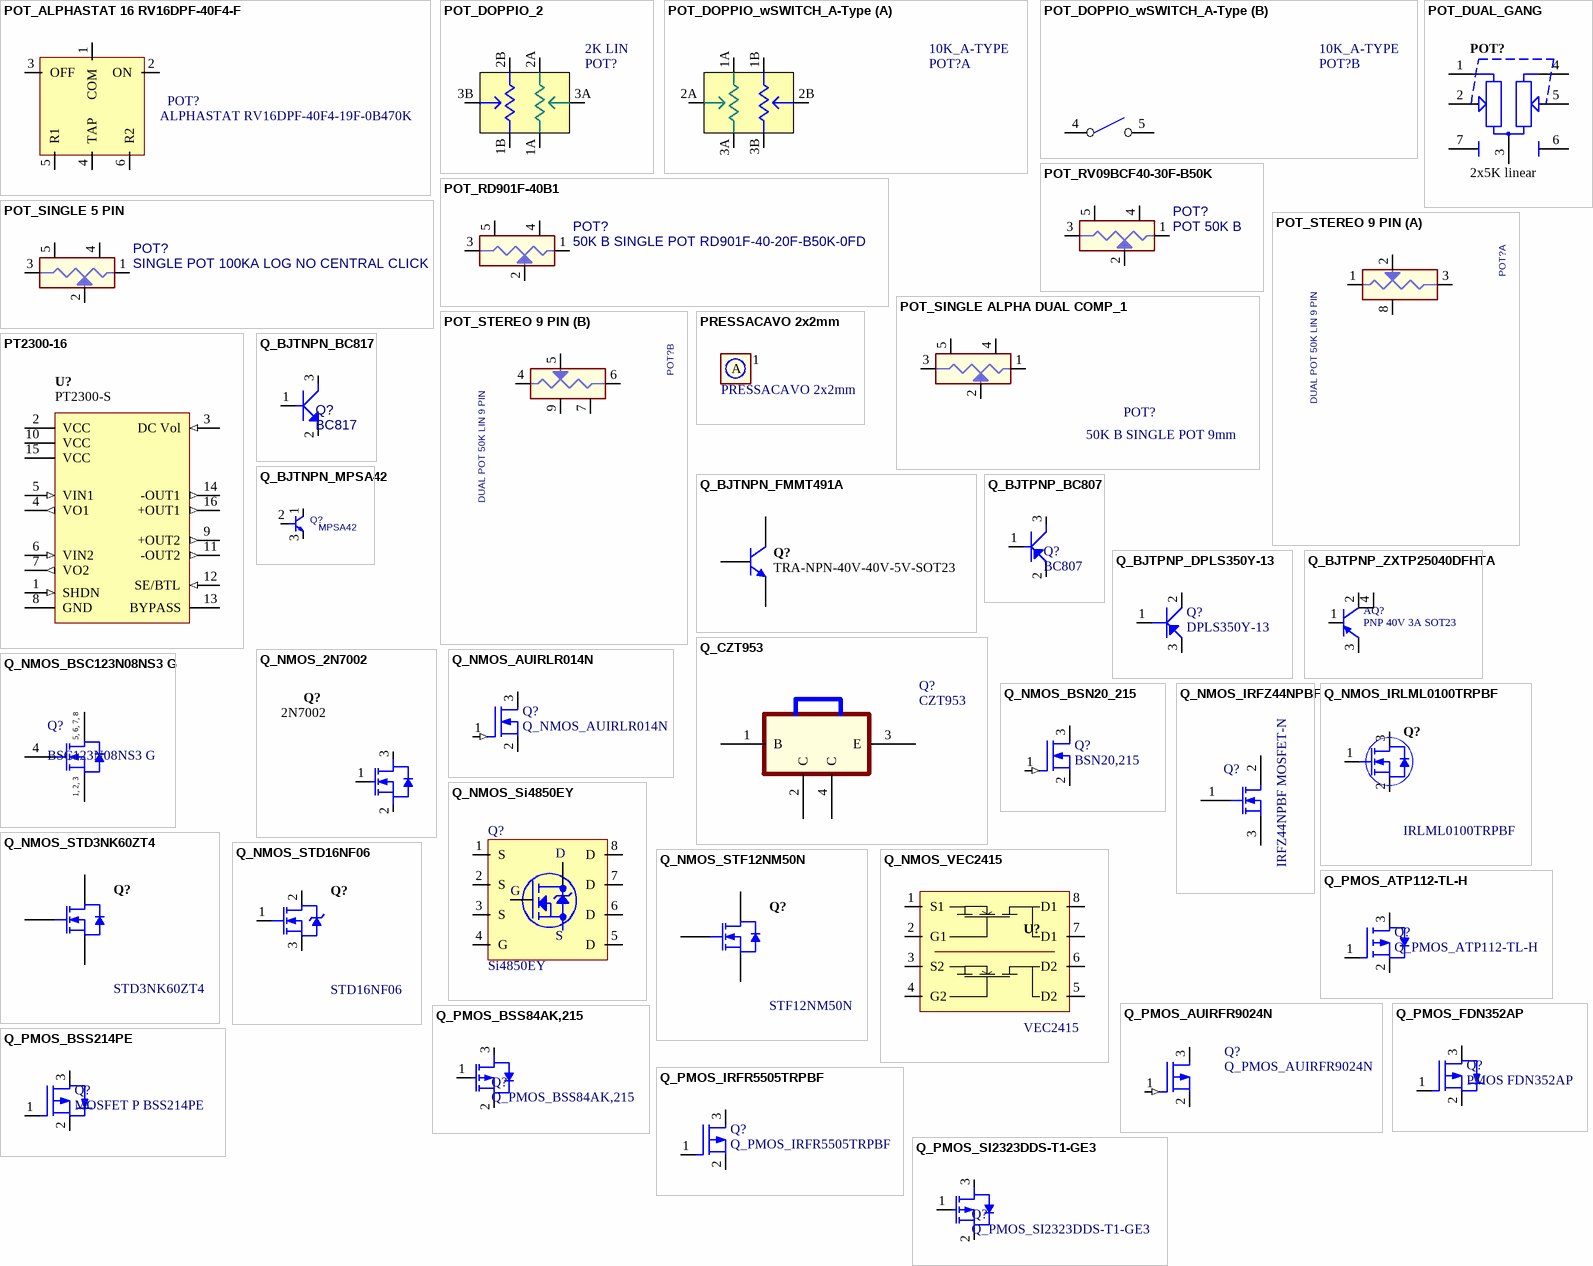
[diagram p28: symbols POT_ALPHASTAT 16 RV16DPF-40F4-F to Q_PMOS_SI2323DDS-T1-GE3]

## POT_ALPHASTAT 16 RV16DPF-40F4-F
designator POT?, comment ALPHASTAT RV16DPF-40F4-19F-0B470K
Hpcode: POTSWB470K; Aggiornato: NO; Costo: 0
footprint RV16DPF-40F4_POT
pins: 1 COM, 2 ON, 3 OFF, 4 TAP, 5 R1, 6 R2

## POT_DOPPIO_2
designator POT?, comment 2K LIN
POT-DOPPIO_2; Costo: 0; Aggiornato: NO
footprint POT-BOURNS-PDB182_4
pins: 1A, 1B, 2A, 2B, 3A, 3B

## POT_DOPPIO_wSWITCH_A-Type
designator POT?, comment 10K_A-TYPE
TRIMMER ALPHA 9mm with SWITCH A-TYPE_RD902F-20-15K-A10K; Costo: 0; Aggiornato: s; Detail: TRIMMER ALPHA 9mm with SWITCH_A-TYPE_RD902F-20-15K-A10K
footprint TRIMMER ALPS 9mm RK0971221Z0X
part A pins: 1A, 1B, 2A, 2B, 3A, 3B
part B pins: 4 NC, 5 COMMON

## POT_DUAL_GANG
designator POT?, comment 2x5K linear
Potentiometer, 2 x 5K Linear 9mm PCB Mount Fluted Shaft; Costo: 0; Aggiornato: NO
footprint POT-R0911G-A1
3D model Shaft
pins: 1, 2, 3, 4, 5, 6, 7

## POT_RD901F-40B1
designator POT?, comment 50K B SINGLE POT RD901F-40-20F-B50K-0FD
TRIMMER ALPHA 9MM RD901F-40B1; Costo: 0,66; Aggiornato: NO; ContoLavoro: 0
footprint TRIMMER ALPHA 9MM RD901F-40B1
pins: 1 A, 2 B, 3 C, 4 SH1, 5 SH2

## POT_RV09BCF40-30F-B50K
designator POT?, comment POT 50K B
POT ALPHA 9MM RV09BCF40-30F-B50K; Hpcode: POT09B50KH30; Costo: 0,20; Aggiornato: s; ContoLavoro: 1
footprint TRIMMER ALPHA 9MM RV09AC
footprint TRIMMER ALPHA 9MM RV09AC - KNOB-POT
pins: 1 A, 2 B, 3 C, 4 SH1, 5 SH2

## POT_SINGLE 5 PIN
designator POT?, comment SINGLE POT 100KA LOG NO CENTRAL CLICK
100KA LOG 9MM VERT ROTARY POT POT RV09BCF40-30F-A100K L=30MM NO CENTRAL CLICK; Detail: ALPHA 9MM RV09AC; Hpcode: PO9V104A30; Value: 100K; Costo: 0
footprint TRIMMER ALPHA 9MM RV09AC
pins: 1 A, 2 B, 3 C, 4 SH1, 5 SH2

## POT_SINGLE ALPHA DUAL COMP_1
designator POT?, comment 50K B SINGLE POT 9mm
50K LINEAR 9mm L=17.5mm POTENTIOMETER SOUNDWELL RA0901N0XOK-HA1-B503-T1-FA175B  ALT: ALPS RK09D1130A1N ALT:RS 729-3653; HPcode: POT09B50KH22; Costo: 0; Aggiornato: NO
footprint TRIMMER ALPHA 9MM RV09AC
pins: 1 A, 2 B, 3 C, 4 SH1, 5 SH2

## POT_STEREO 9 PIN
designator POT?, comment DUAL POT 50K LIN 9 PIN
50KB 9MM VERT ROTARY POTENTIOMETER L=30MM CENTRAL CLICK; Detail: ALPHA 9MM RV09AC; Hpcode: PO9V503B30; Costo: 0; Aggiornato: NO
footprint TRIMMER ALPHA 9MM RV09AC
part A pins: 1 1A, 2 2A, 3 3A, 8 SH1
part B pins: 4 1B, 5 2B, 6 3B, 7 DUMMY, 9 SH2

## PRESSACAVO 2x2mm
designator P?  (no BOM)
Costo: 0; Aggiornato: NO
footprint PRESSACAVO_2x2mm (Footprint not found)
pins: 1 A

## PT2300-16
designator U?, comment PT2300-S
PT2300, 2W x 2 Class AB Audio Power Amplifier; Supply Voltage: 5 V; Aggiornato: NO; Costo: 0
footprint SOIC127P1030-16N
pins: 1 SHDN (in), 2 VCC (power), 3 DC Vol (in), 4 VO1 (out), 5 VIN1 (in), 6 VIN2 (in), 7 VO2 (out), 8 GND (power), 9 +OUT2 (out), 10 VCC (power), 11 -OUT2 (out), 12 SE/BTL (in), 13 BYPASS, 14 -OUT1 (out), 15 VCC (power), 16 +OUT1 (out)

## Q_BJTNPN_BC817
designator Q?, comment BC817
Costo: 0,014; Aggiornato: NO; ContoLavoro: 0
footprint SOT-23_UP
simulation model QBC817
pins: 1 G, 2 S, 3 D

## Q_BJTNPN_FMMT491A
designator Q?, comment TRA-NPN-40V-40V-5V-SOT23
Transistor, FMMT491A Small Signal NPN; Aggiornato: NO; Costo: 0
footprint SOT95P230-3C
pins: 1 B, 2 E, 3 C

## Q_BJTNPN_MPSA42
designator Q?, comment MPSA42
Hpcode: TRANSMPSA42; Costo: 0; Aggiornato: NO
footprint TO92/100/321
pins: 1 COLLECTOR, 2 BASE (in), 3 EMITTER

## Q_BJTPNP_BC807
designator Q?, comment BC807
Aggiornato: NO; Costo: 0,04; ContoLavoro: 0
footprint SOT-23_UP
pins: 1 G, 2 S, 3 D

## Q_BJTPNP_DPLS350Y-13
designator Q?, comment DPLS350Y-13
Detail: € RS pz>50; Aggiornato: S; Costo: 0,10; ContoLavoro: 0
footprint SOT89_DPLS350Y
pins: 1 B, 2 E, 3 C

## Q_BJTPNP_ZXTP25040DFHTA
designator AQ?, comment PNP 40V 3A SOT23
PNP Bipolar Transistor SOT23; Part field 1: Zetex ZXTP25040DFHTA; Aggiornato: NO; Costo: 0
footprint SOT23-3N (SOT23, 3-Leads, Body 2.9x1.3mm, Pitch 0.95mm, Lead Span 2.5mm, IPC Medium Density)
pins: 1 B, 2 C, 3 E, 4 C2
2 alternate drawings of the same symbol

## Q_CZT953
designator Q?, comment CZT953
CZT953 SMD TRANSISTOR; Aggiornato: N; Costo: 0
footprint SOT223
pins: 1 B, 2 C, 3 E, 4 C

## Q_NMOS_2N7002
designator Q?, comment 2N7002
N-channel Small Signal MOSFET; Aggiornato: S; Costo: 0,04; ContoLavoro: 0
footprint SOT-23_UP
pins: 1 G, 2 S, 3 D

## Q_NMOS_AUIRLR014N
designator Q?
MOSFET N AUIRLR014N; Costo: 0,40; Aggiornato: NO; ContoLavoro: 0
footprint TO252AA_DPACK_3PIN
pins: 1 GATE (in) "1", 2 SOURCE "2", 3 DRAIN "3"

## Q_NMOS_BSC123N08NS3 G
designator Q?, comment BSC123N08NS3 G
N-Channel OptiMOS 3 Power-Transistor, 80 V VDS, 55 A ID, -55 to 150 degC, PG-TDSON-8-1, Reel, Green; Manufacturer: Infineon; Green: TRUE; ID (max): 55 A; IDpuls (max): 220 A; Polarity: N; Ptot (max): 66 W; QG: 19 nC; RDS (on) (max): 12.3 mOhm; Rth: 1.9 K/W; RthJA (max): 60 K/W; VDS (max): 80 V; VGS(th) (max): 3.5 V; VGS(th) (min): 2 V; Aggiornato: s; ContoLavoro: 0; Costo: 0,5
footprint INF-PG-TDSON-8-1_V_MOD (Footprint not found)
pins: 1 SOURCE, 2 SOURCE, 3 SOURCE, 4 GATE, 5 DRAIN, 6 DRAIN, 7 DRAIN, 8 DRAIN

## Q_NMOS_BSN20_215
designator Q?, comment BSN20,215
Costo: 0,098; Aggiornato: NO; ContoLavoro: 0
footprint SOT-23_UP
footprint SOT-23/TO-236_AB_JEDEC (Footprint not found)
pins: 1 GATE (in) "1", 2 SOURCE "2", 3 DRAIN "3"

## Q_NMOS_IRFZ44NPBF
designator Q?, comment IRFZ44NPBF MOSFET-N
N-Channel MOSFET; Aggiornato: NO; Costo: 0
footprint TO220_123
pins: 1 G "1", 2 D "2", 3 S "3"

## Q_NMOS_IRLML0100TRPBF
designator Q?, comment IRLML0100TRPBF
N Channel Power MOS IRLML0100TRPBF; Aggiornato: S; Costo: 0,15; ContoLavoro: 0
footprint SOT-23_UP
footprint SOT-23_MINIMAL (SOT-23_minimal)
pins: 1 G, 2 S, 3 D

## Q_NMOS_Si4850EY
designator Q?, comment Si4850EY
Costo: 0; Aggiornato: NO
footprint SO8
pins: 1 S, 2 S, 3 S, 4 G, 5 D, 6 D, 7 D, 8 D

## Q_NMOS_STD3NK60ZT4
designator Q?, comment STD3NK60ZT4
MOSFET 600V 3.6/10V 11.8 2.4A; Aggiornato: NO; Costo: 0
pins: 1 G, 2 D, 3 S

## Q_NMOS_STD16NF06
designator Q?, comment STD16NF06
N Channel Power MOS FET STD16NF06; Aggiornato: S; Costo: 0,2; ContoLavoro: 0
footprint TO252 (Footprint not found)
pins: 1 G, 2 D, 3 S

## Q_NMOS_STF12NM50N
designator Q?, comment STF12NM50N
MOSFET 500V 12A N-Channel Power MOSFET; Costo: 0; Aggiornato: NO
pins: 1 G, 2 D, 3 S

## Q_NMOS_VEC2415
designator U?, comment VEC2415
Double N Channel Power MOS VEC2415; Aggiornato: S; Costo: 0,35; ContoLavoro: 0
footprint VEC8
pins: 1 S1, 2 G1, 3 S2, 4 G2, 5 D2, 6 D2, 7 D1, 8 D1

## Q_PMOS_ATP112-TL-H
designator Q?
MOSFET P ATP112-TL-H; Costo: 0,267; Detail: prezzo RS<10pz; ContoLavoro: 0; Aggiornato: s
footprint TO252_ATPAK
pins: 1 GATE, 2 SOURCE, 3 DRAIN

## Q_PMOS_AUIRFR9024N
designator Q?
MOSFET P AUIRFR9024N; Costo: 0,406; Detail: prezzo RS<20pz; ContoLavoro: 0
footprint TO252AA_DPACK_3PIN (Footprint not found)
pins: 1 GATE (in), 2 SOURCE, 3 DRAIN

## Q_PMOS_BSS84AK,215
designator Q?
BSS84AK,215; Costo: 0,04; ContoLavoro: 0
footprint SOT-23_UP
pins: 1 G, 2 S, 3 D

## Q_PMOS_BSS214PE
designator Q?, comment MOSFET P BSS214PE
BSS214PE; Costo: 0,074; Detail: € RS pz>100; ContoLavoro: 0
footprint SOT-23_UP
pins: 1 GATE, 2 SOURCE, 3 DRAIN

## Q_PMOS_FDN352AP
designator Q?, comment PMOS FDN352AP
FDN352AP; Costo: 0,15; Detail: € Farnell pz>80; ContoLavoro: 0; Aggiornato: S
footprint SOT-23_UP
pins: 1 GATE, 2 SOURCE, 3 DRAIN

## Q_PMOS_IRFR5505TRPBF
designator Q?
MOSFET P IRFR5505TRPBF; Costo: 0,229; Detail: prezzo RS<20pz; ContoLavoro: 0
footprint TO252AA_DPACK_3PIN (Footprint not found)
pins: 1 GATE, 2 SOURCE, 3 DRAIN

## Q_PMOS_SI2323DDS-T1-GE3
designator Q?
SI2323DDS-T1-GE3; Costo: 0,2; ContoLavoro: 0
footprint SOT-23_UP
pins: 1 G, 2 S, 3 D

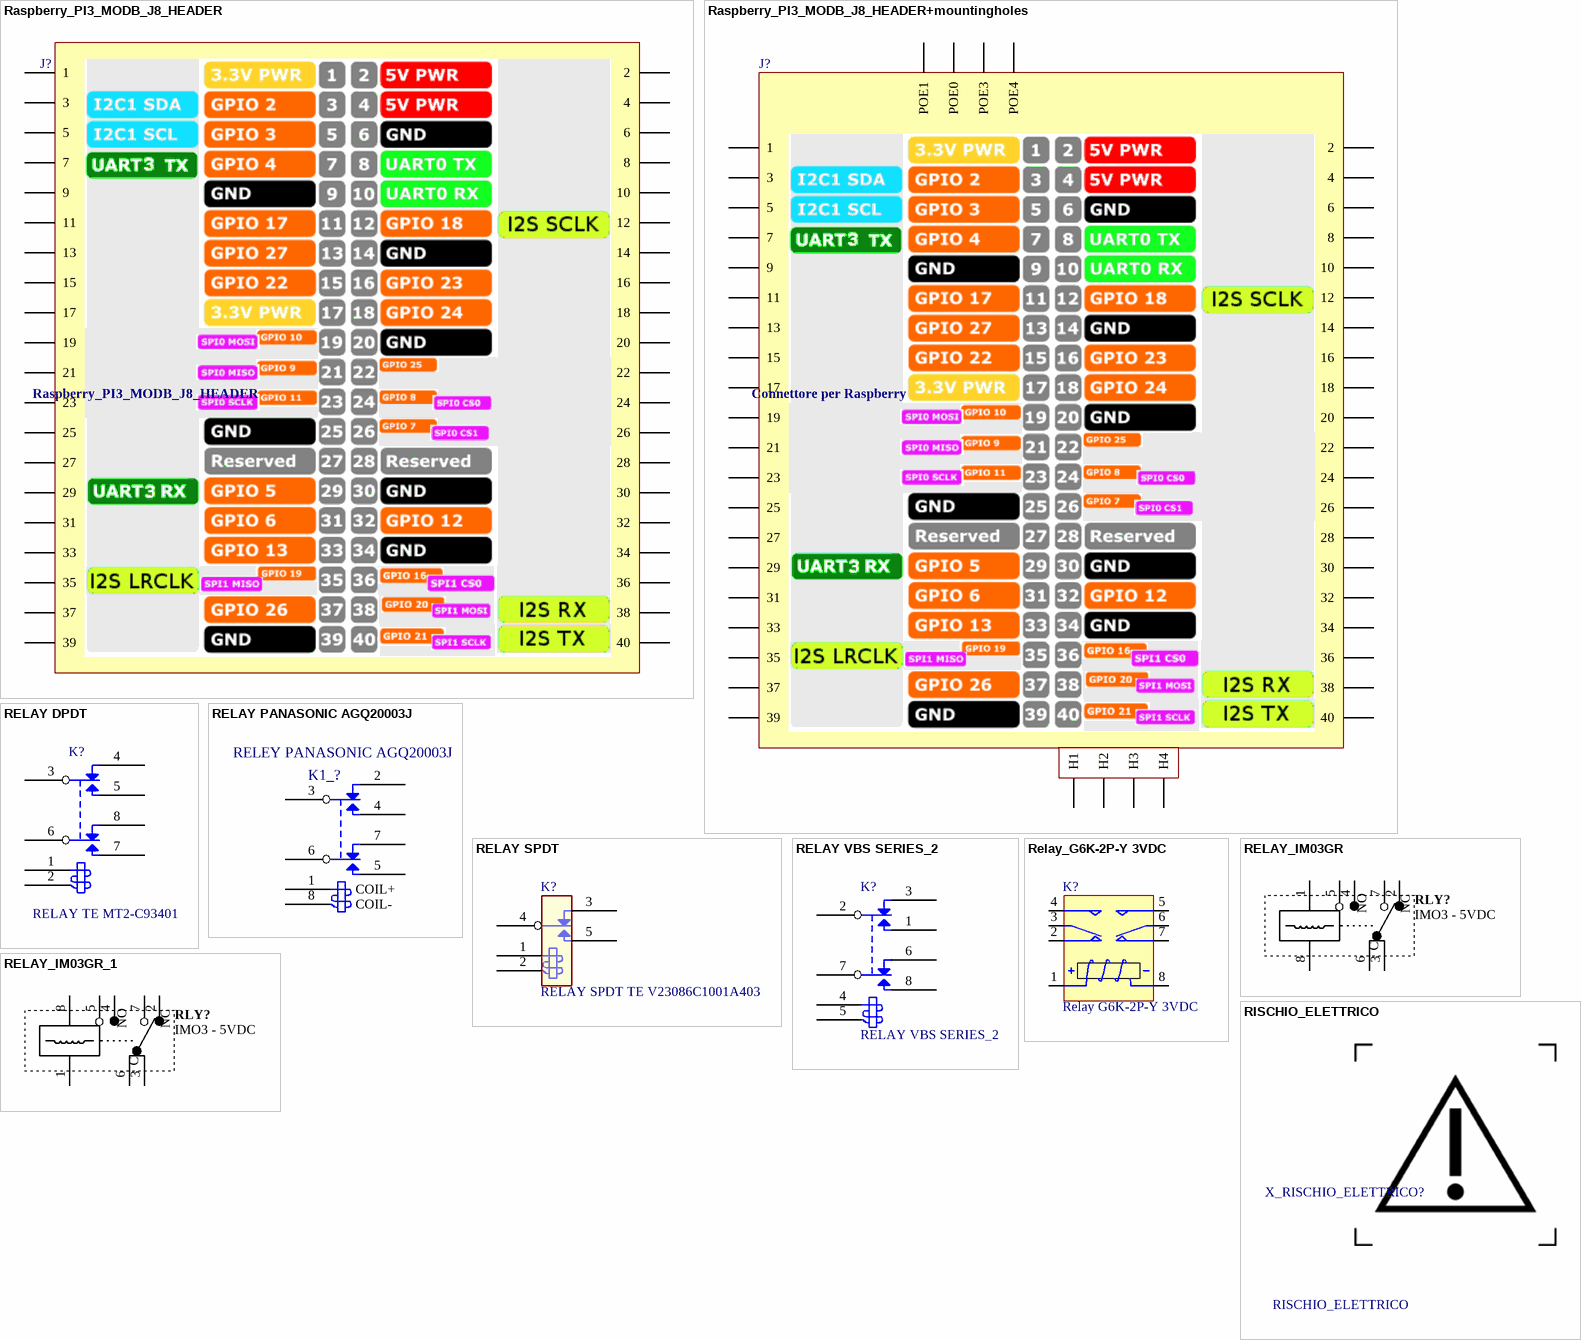
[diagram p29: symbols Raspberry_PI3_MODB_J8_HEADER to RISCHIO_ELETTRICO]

## Raspberry_PI3_MODB_J8_HEADER
designator J?
Hpcode: CONF2P548H5; Aggiornato: S; Costo: 0,30338; ContoLavoro: 1
footprint HEADER PBD-40 2X20_FEMALE
pins: 1, 2, 3, 4, 5, 6, 7, 8, 9, 10, 11, 12, 13, 14, 15, 16, 17, 18, 19, 20, 21, 22, 23, 24, 25, 26, 27, 28, 29, 30, 31, 32, 33, 34, 35, 36, 37, 38, 39, 40

## Raspberry_PI3_MODB_J8_HEADER+mountingholes
designator J?, comment Connettore per Raspberry
Hpcode: CONF2P548H5; Aggiornato: S; Costo: 0,30338; ContoLavoro: 1
footprint HEADER PBD-40 2X20_FEMALE_+mountingholes_for_Rasp_PI3_with3D (HEADER PBD-40 2X20_FEMALE_+mountingholes_for_Rasp_PI3)
footprint HEADER PBD-40 2X20_FEMALE_+mountingholes_for_Rasp_PI3
footprint HEADER PBD-40 2X20_FEMALE_+mountingholes_+poe_for_Rasp_PI3
pins: 1, 2, 3, 4, 5, 6, 7, 8, 9, 10, 11, 12, 13, 14, 15, 16, 17, 18, 19, 20, 21, 22, 23, 24, 25, 26, 27, 28, 29, 30, 31, 32, 33, 34, 35, 36, 37, 38, 39, 40, 41 POE1, 42 POE0, 43 POE3, 44 POE4, H1, H2, H3, H4

## RELAY DPDT
designator K?, comment RELAY TE MT2-C93401
Costo: 1,59; Aggiornato: n; ContoLavoro: 0
footprint RELAY 24V
pins: 1 COIL1, 2 COIL2, 3 COMMON1, 4 NC1, 5 NO1, 6 COMMON2, 7 NO2, 8 NC2

## RELAY PANASONIC AGQ20003J
designator K1_?, comment RELEY PANASONIC AGQ20003J
Hpcode: SWRELAYS001; Costo: 1,55; Aggiornato: NO; ContoLavoro: 0
footprint RELAY_OMRON_G6K-2P-Y
pins: 1      COIL+, 2 NC1, 3 COMMON1, 4 NO1, 5 NO2, 6 COMMON2, 7 NC2, 8      COIL-

## RELAY SPDT
designator K?, comment RELAY SPDT TE V23086C1001A403
Costo: 0,62; Aggiornato: NO; ContoLavoro: 0
footprint RELAY TE V23086C1001A403
pins: 1 COIL1, 2 COIL2, 3 NC, 4 COMMON, 5 NO

## RELAY VBS SERIES_2
designator K?
Aggiornato: NO; Costo: 0
footprint RELAY VSB SERIES
pins: 1 NO1, 2 COMMON1, 3 NC1, 4 COIL1, 5 COIL2, 6 NC2, 7 COMMON2, 8 NO2

## Relay_G6K-2P-Y 3VDC
designator K?, comment Relay G6K-2P-Y 3VDC
Relay_G6K-2P-Y 3VDC; Costo: 2; Aggiornato: NO; ContoLavoro: 0
footprint RELAY_OMRON_G6K-2P-Y
pins: 1 +, 2 T1, 3 COM, 4 T2, 5 T2, 6 COM, 7 T1, 8 -

## RELAY_IM03GR
designator RLY?, comment IMO3 - 5VDC
Relay, Tyco IM03GR; Rated Voltage: mV; Switch Type: SPDT; Aggiornato: NO; Costo: 0
footprint IM03GR
pins: 1, 2, 3, 4, 5, 6, 7, 8

## RELAY_IM03GR_1
designator RLY?, comment IMO3 - 5VDC
Relay, Tyco IM03GR; Rated Voltage: mV; Switch Type: DPDT; Aggiornato: NO; Costo: 0
footprint IM03GR
pins: 1 +, 2, 3, 4, 5, 6, 7, 8 -

## RISCHIO_ELETTRICO
designator X_RISCHIO_ELETTRICO?
Costo: 0; Aggiornato: NO
footprint RISCHIO_ELETTRICO_7mmx7mm (RISCHIO ELETTRICO 7mmx7mm)
footprint RISCHIO_ELETTRICO_13mmx13mm (RISCHIO ELETTRICO 13mmx13mm)
footprint RISCHIO_ELETTRICO_30mmx30mm (RISCHIO ELETTRICO 30mmx30mm)
footprint RISCHIO_FOLGORAZIONE (RISCHIO FOLGORAZIONE)
footprint RISCHIO_ELETTRICO_23mmx23mm (RISCHIO ELETTRICO 23mmx23mm)

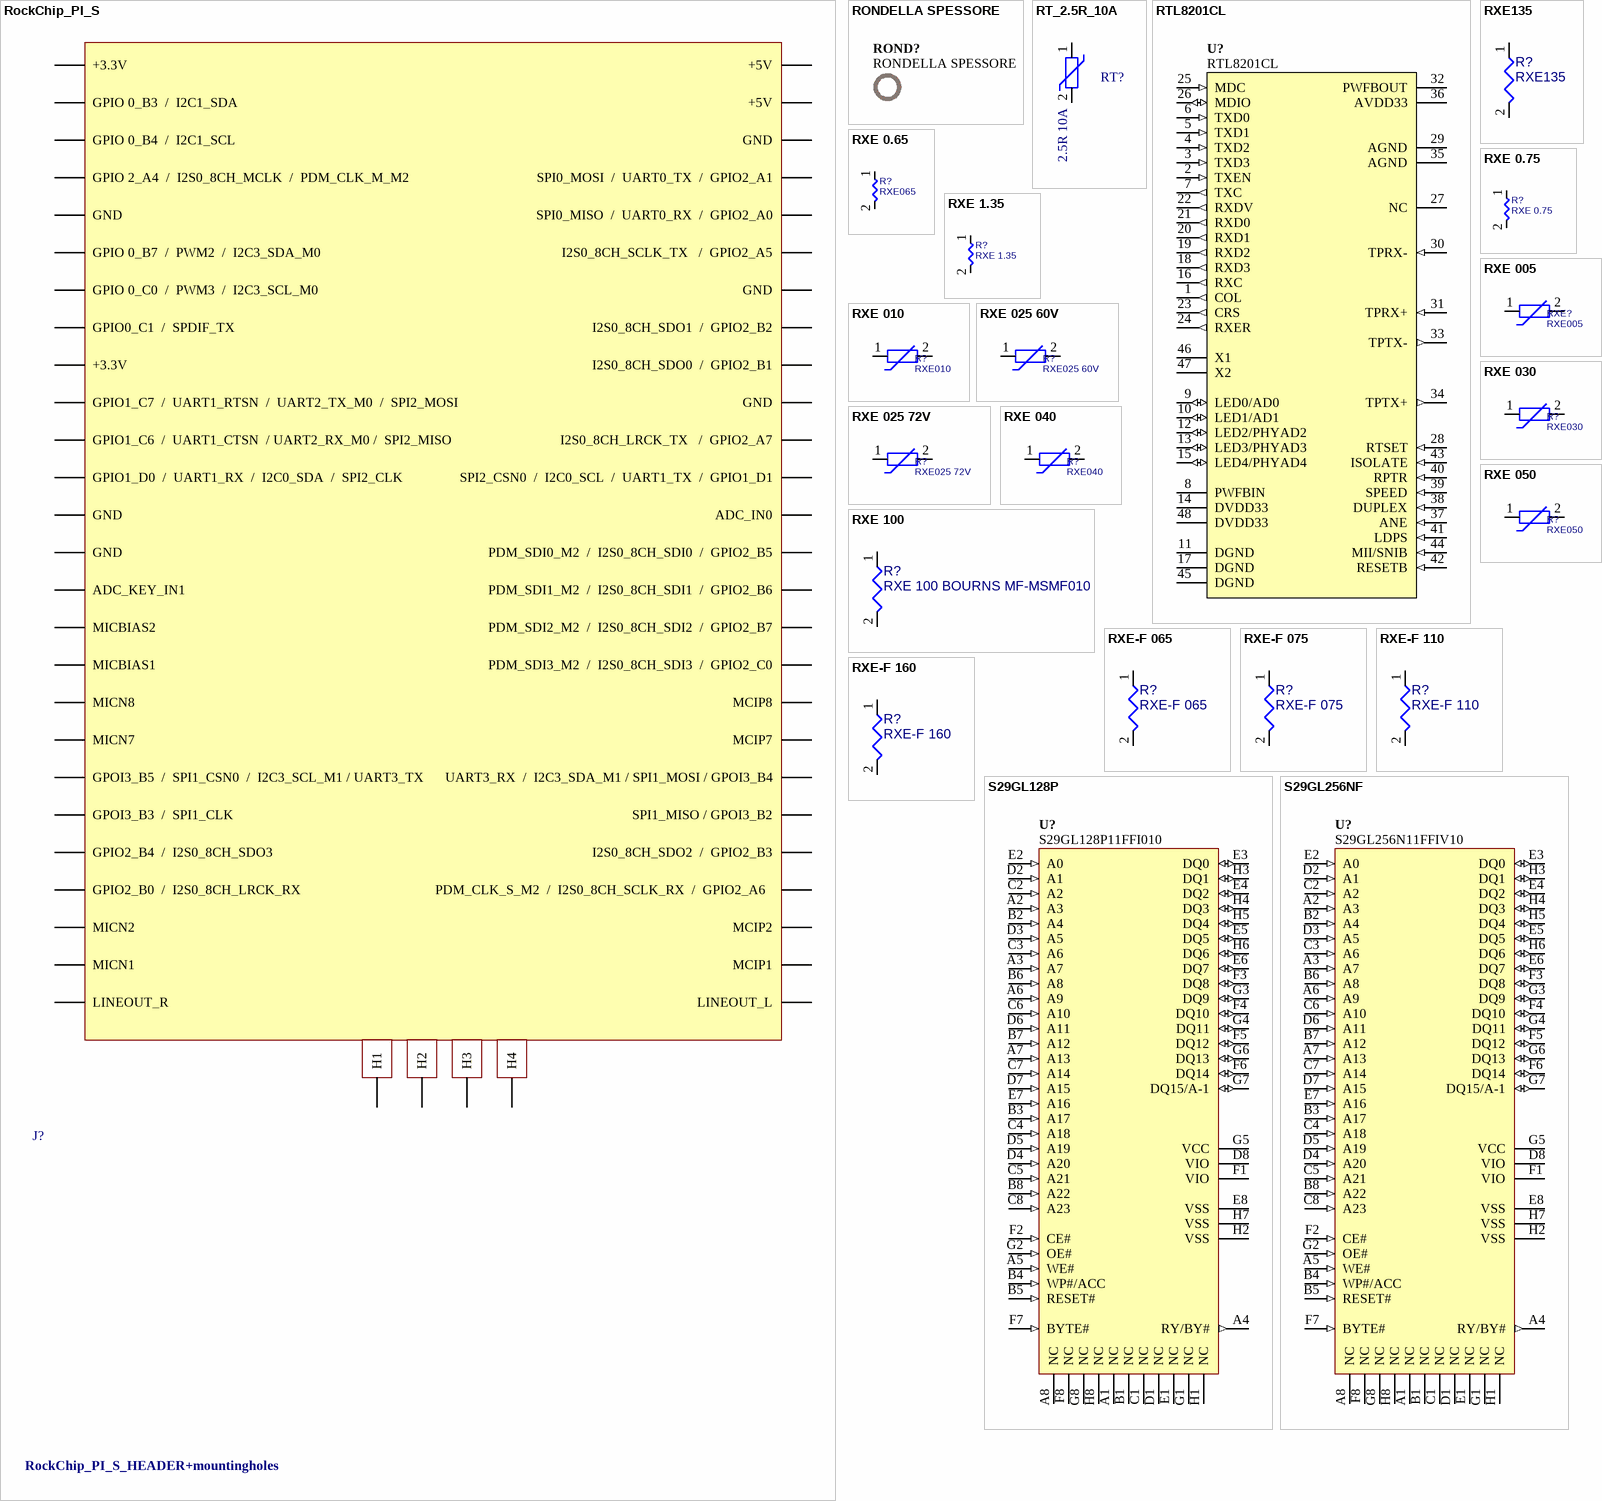
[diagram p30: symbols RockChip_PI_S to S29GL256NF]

## RockChip_PI_S
designator J?, comment RockChip_PI_S_HEADER+mountingholes
Hpcode: CONF2P548H5; Aggiornato: S; Costo: 0,30338; ContoLavoro: 1
footprint ROCKCHIP_PI_S +MOUNTINGHOLES
pins: 1 +3.3V, 1. GND, 2 +5V, 2. PDM_SDI0_M2  /  I2S0_8CH_SDI0  /  GPIO2_B5, 3 GPIO 0_B3  /  I2C1_SDA, 3. ADC_KEY_IN1, 4 +5V, 4. PDM_SDI1_M2  /  I2S0_8CH_SDI1  /  GPIO2_B6, 5 GPIO 0_B4  /  I2C1_SCL, 5. MICBIAS2, 6 GND, 6. PDM_SDI2_M2  /  I2S0_8CH_SDI2  /  GPIO2_B7, 7 GPIO 2_A4  /  I2S0_8CH_MCLK  /  PDM_CLK_M_M2, 7. MICBIAS1, 8 SPI0_MOSI  /  UART0_TX  /  GPIO2_A1, 8. PDM_SDI3_M2  /  I2S0_8CH_SDI3  /  GPIO2_C0, 9 GND, 9. MICN8, 10 SPI0_MISO  /  UART0_RX  /  GPIO2_A0, 10. MCIP8, 11 GPIO 0_B7  /  PWM2  /  I2C3_SDA_M0, 11. MICN7, 12 I2S0_8CH_SCLK_TX   /  GPIO2_A5, 12. MCIP7, 13 GPIO 0_C0  /  PWM3  /  I2C3_SCL_M0, 13. GPOI3_B5  /  SPI1_CSN0  /  I2C3_SCL_M1 / UART3_TX, 14 GND, 14. UART3_RX  /  I2C3_SDA_M1 / SPI1_MOSI / GPOI3_B4, 15 GPIO0_C1  /  SPDIF_TX, 15. GPOI3_B3  /  SPI1_CLK, 16 I2S0_8CH_SDO1  /  GPIO2_B2, 16. SPI1_MISO / GPOI3_B2, 17 +3.3V, 17. GPIO2_B4  /  I2S0_8CH_SDO3, 18 I2S0_8CH_SDO0  /  GPIO2_B1, 18. I2S0_8CH_SDO2  /  GPIO2_B3, 19 GPIO1_C7  /  UART1_RTSN  /  UART2_TX_M0  /  SPI2_MOSI, 19. GPIO2_B0  /  I2S0_8CH_LRCK_RX, 20 GND, 20. PDM_CLK_S_M2  /  I2S0_8CH_SCLK_RX  /  GPIO2_A6  , 21 GPIO1_C6  /  UART1_CTSN  / UART2_RX_M0 /  SPI2_MISO, 21. MICN2, 22 I2S0_8CH_LRCK_TX   /  GPIO2_A7, 22. MCIP2, 23 GPIO1_D0  /  UART1_RX  /  I2C0_SDA  /  SPI2_CLK, 23. MICN1, 24 SPI2_CSN0  /  I2C0_SCL  /  UART1_TX  /  GPIO1_D1, 24. MCIP1, 25 GND, 25. LINEOUT_R, 26 ADC_IN0, 26. LINEOUT_L, H1, H2, H3, H4

## RONDELLA SPESSORE
designator ROND?  (mechanical)
Aggiornato: NO; Costo: 0,013; Detail: 0,013€ costo standard Esolver; HPcode: RONP0410PB020; ContoLavoro: 1
pins: 1 hidden

## RT_2.5R_10A
designator RT?, comment 2.5R 10A
NTC Resistor 2.5R 10A; Costo: 0; Aggiornato: NO
pins: 1, 2

## RTL8201CL
designator U?
RTL8201CL-VD, Single-Chip/Single-Port 10/100 Fast Ethernet Phyceiver; Aggiornato: NO; Costo: 0
footprint TSQFP50P900X900-48
pins: 1 COL (out), 2 TXEN (in), 3 TXD3 (in), 4 TXD2 (in), 5 TXD1 (in), 6 TXD0 (in), 7 TXC (out), 8 PWFBIN (power), 9 LED0/AD0 (io), 10 LED1/AD1 (io), 11 DGND (power), 12 LED2/PHYAD2 (io), 13 LED3/PHYAD3 (io), 14 DVDD33 (power), 15 LED4/PHYAD4 (io), 16 RXC (out), 17 DGND (power), 18 RXD3 (out), 19 RXD2 (out), 20 RXD1 (out), 21 RXD0 (out), 22 RXDV (out), 23 CRS (out), 24 RXER (out), 25 MDC (in), 26 MDIO (io), 27 NC, 28 RTSET (in), 29 AGND (power), 30 TPRX- (in), 31 TPRX+ (in), 32 PWFBOUT (power), 33 TPTX- (out), 34 TPTX+ (out), 35 AGND (power), 36 AVDD33 (power), 37 ANE (in), 38 DUPLEX (in), 39 SPEED (in), 40 RPTR (in), 41 LDPS (in), 42 RESETB (in), 43 ISOLATE (in), 44 MII/SNIB (in), 45 DGND (power), 46 X1, 47 X2, 48 DVDD33 (power)

## RXE135
designator R?
RXE 135 TYCO RXEF135 ALT:RS 517-6691; Costo: 0; Aggiornato: NO
footprint RAD 12X2
pins: 1, 2

## RXE 0.65
designator R?, comment RXE065
RXE 0.65 Amperes; Costo: 0; Aggiornato: NO
footprint RAD 7X2
pins: 1, 2

## RXE 0.75
designator R?
RXE 0.75 Ampere WELT MF-R075; Costo: 0; Aggiornato: NO
footprint RXE_075_ORIZ
footprint RXE075
pins: 1, 2

## RXE 1.35
designator R?
RXE 1.35 Ampere WELT MF-R135; Detail: RXE 135; Costo: 0; Aggiornato: NO
footprint RAD 7X2
footprint RXE150
pins: 1, 2

## RXE 005
designator RXE?, comment RXE005
RXE 0.1A; Detail: 0,216€ RS>100; Costo: 0,216; Aggiornato: S; ContoLavoro: 0
footprint RXE020
pins: 1, 2

## RXE 010
designator R?, comment RXE010
RXE 200mA; Costo: 0; Aggiornato: SI
footprint RXE020
footprint RXE020 piegata
footprint RXE020_PIEGATA_SOLO_3D
pins: 1, 2

## RXE 025 60V
designator R?, comment RXE025 60V
RXE 0.25 Amperes 60V; Costo: 0; Aggiornato: SI
footprint RXE020
pins: 1, 2

## RXE 025 72V
designator R?, comment RXE025 72V
RXE 0.25 Amperes 72V; Detail: prezzo RS >100pz; Costo: 0,331; Aggiornato: SI; ContoLavoro: 0
footprint RXE020
pins: 1, 2

## RXE 030
designator R?, comment RXE030
RXE 0.30 Amperes; Costo: 0; Aggiornato: SI
footprint RXE020
pins: 1, 2

## RXE 040
designator R?, comment RXE040
RXE 0.80 Amperes; Detail: WELT; Costo: 0,12; Aggiornato: SI; ContoLavoro: 0
footprint RXE020
pins: 1, 2

## RXE 050
designator R?, comment RXE050
RXE 1.00 Amperes; Detail: WELT; Costo: 0,12; Aggiornato: SI; ContoLavoro: 0
footprint RXE020
footprint RXE020 piegata
footprint RXE020_PIEGATA_SOLO_3D
pins: 1, 2

## RXE 100
designator R?, comment RXE 100 BOURNS MF-MSMF010
RXE 100 BOURNS MF-MSMF010 ALT:TYCO MINISMDCO10F-2, RS 647-8134; Detail: RXE100; Costo: 0; Aggiornato: NO
footprint RXE_MF_MSMF
pins: 1, 2

## RXE-F 065
designator R?
RXE065 TYCO RXEF065 SETCROSSOVER CODE PTC065 ALT:RS 517-6641; Costo: 0,172; Aggiornato: NO; ContoLavoro: 0
footprint RXE020
pins: 1, 2

## RXE-F 075
designator R?
RXE075 TYCO RXEF075 SETCROSSOVER CODE PTC075 ALT:RS; Costo: 0; Aggiornato: NO
footprint RXE020
pins: 1, 2

## RXE-F 110
designator R?
Costo: 0; Aggiornato: SI
footprint RXE075
pins: 1, 2

## RXE-F 160
designator R?
Detail: RS >500pz; Costo: 0,3; Aggiornato: SI; ContoLavoro: 0
footprint RXE075
pins: 1, 2

## S29GL128P
designator U?, comment S29GL128P11FFI010
IC Flash, S29GL128P11FFI010 128 Megabit 3.0V Page Mode Flash Memory; Bit Width: Bits; Supply Voltage: 3.3 V; Aggiornato: NO; Costo: 0
footprint BGA100P8X8-64
pins: A1 NC "Not connected to the die", A2 A3 (in) "Address Input, Bit 2", A3 A7 (in) "Address Input, Bit 6", A4 RY/BY# (out) "Data Input/Output, Bit 1", A5 WE# (in) "Not connected to the die", A6 A9 (in) "Address Input, Bit 8", A7 A13 (in) "Address Input, Bit 11", A8 NC "Data Input/Output, Bit 14", B1 NC "Not connected to the die", B2 A4 (in) "Address Input, Bit 3", B3 A17 (in) "Address Input, Bit 15", B4 WP#/ACC (in) "Not connected to the die", B5 RESET# (in) "Data Input/Output, Bit 0", B6 A8 (in) "Address Input, Bit 7", B7 A12 (in) "Chip Enable Input", B8 A22 (in) "Address Input, Bit 20", C1 NC "Not connected to the die", C2 A2 (in) "Address Input, Bit 1", C3 A6 (in) "Address Input, Bit 5", C4 A18 (in) "Address Input, Bit 16", C5 A21 (in) "Address Input, Bit 19", C6 A10 (in) "Address Input, Bit 9", C7 A14 (in) "Address Input, Bit 12", C8 A23 (in) "Output Enable Input", D1 NC "Not connected to the die", D2 A1 (in) "Address Input, Bit 23", D3 A5 (in) "Address Input, Bit 4", D4 A20 (in) "Address Input, Bit 18", D5 A19 (in) "Address Input, Bit 17", D6 A11 (in) "Address Input, Bit 10", D7 A15 (in) "Address Input, Bit 13", D8 VIO (power) "Data Input/Output, Bit 3", E1 NC "Not connected to the die", E2 A0 (in) "Address Input, Bit 22", E3 DQ0 (io) "Device Ground", E4 DQ2 (io) "Acceleration Input", E5 DQ5 (io) "Data Input/Output, Bit 4", E6 DQ7 (io) "Data Input/Output, Bit 6", E7 A16 (in) "Address Input, Bit 14", E8 VSS (power) "Not connected to the die", F1 VIO (power) "Select Word or Byte Mode", F2 CE# (in) "Device Ground", F3 DQ8 (io) "Data Input/Output, Bit 7", F4 DQ10 (io) "Data Input/Output, Bit 9", F5 DQ12 (io) "Data Input/Output, Bit 11", F6 DQ14 (io) "Data Input/Output, Bit 13", F7 BYTE# (in) "Address Input, Bit 21", F8 NC "Data Input/Output, Bit 15", G1 NC "Not connected to the die", G2 OE# (in) "Output Buffer Power", G3 DQ9 (io) "Data Input/Output, Bit 8", G4 DQ11 (io) "Data Input/Output, Bit 10", G5 VCC (power) "Data Input/Output, Bit 2", G6 DQ13 (io) "Data Input/Output, Bit 12", G7 DQ15/A-1 (io) "3 Volt Single Power Supply", G8 NC "Ready/Busy Output (FBGA only)", H1 NC "Not connected to the die", H2 VSS (power) "Not connected to the die", H3 DQ1 (io) "Write Enable Input", H4 DQ3 (io) "Hardware Reset Pin Input", H5 DQ4 (io) "Address Input, Bit 0", H6 DQ6 (io) "Data Input/Output, Bit 5", H7 VSS (power) "Not connected to the die", H8 NC "Not connected to the die"

## S29GL256NF
designator U?, comment S29GL256N11FFIV10
S29GL256N11FFIV10, 256 Megabit (16M x 16) 3.0V Page Mode Flash Memory; Bit Width: Bits; Supply Voltage: mV; Aggiornato: NO; Costo: 0
footprint BGA100P8X8-64
pins: A1 NC "Not connected to the die", A2 A3 (in) "Address Input, Bit 2", A3 A7 (in) "Address Input, Bit 6", A4 RY/BY# (out) "Data Input/Output, Bit 1", A5 WE# (in) "Not connected to the die", A6 A9 (in) "Address Input, Bit 8", A7 A13 (in) "Address Input, Bit 11", A8 NC "Data Input/Output, Bit 14", B1 NC "Not connected to the die", B2 A4 (in) "Address Input, Bit 3", B3 A17 (in) "Address Input, Bit 15", B4 WP#/ACC (in) "Not connected to the die", B5 RESET# (in) "Data Input/Output, Bit 0", B6 A8 (in) "Address Input, Bit 7", B7 A12 (in) "Chip Enable Input", B8 A22 (in) "Address Input, Bit 20", C1 NC "Not connected to the die", C2 A2 (in) "Address Input, Bit 1", C3 A6 (in) "Address Input, Bit 5", C4 A18 (in) "Address Input, Bit 16", C5 A21 (in) "Address Input, Bit 19", C6 A10 (in) "Address Input, Bit 9", C7 A14 (in) "Address Input, Bit 12", C8 A23 (in) "Output Enable Input", D1 NC "Not connected to the die", D2 A1 (in) "Address Input, Bit 23", D3 A5 (in) "Address Input, Bit 4", D4 A20 (in) "Address Input, Bit 18", D5 A19 (in) "Address Input, Bit 17", D6 A11 (in) "Address Input, Bit 10", D7 A15 (in) "Address Input, Bit 13", D8 VIO (power) "Data Input/Output, Bit 3", E1 NC "Not connected to the die", E2 A0 (in) "Address Input, Bit 22", E3 DQ0 (io) "Device Ground", E4 DQ2 (io) "Acceleration Input", E5 DQ5 (io) "Data Input/Output, Bit 4", E6 DQ7 (io) "Data Input/Output, Bit 6", E7 A16 (in) "Address Input, Bit 14", E8 VSS (power) "Not connected to the die", F1 VIO (power) "Select Word or Byte Mode", F2 CE# (in) "Device Ground", F3 DQ8 (io) "Data Input/Output, Bit 7", F4 DQ10 (io) "Data Input/Output, Bit 9", F5 DQ12 (io) "Data Input/Output, Bit 11", F6 DQ14 (io) "Data Input/Output, Bit 13", F7 BYTE# (in) "Address Input, Bit 21", F8 NC "Data Input/Output, Bit 15", G1 NC "Not connected to the die", G2 OE# (in) "Output Buffer Power", G3 DQ9 (io) "Data Input/Output, Bit 8", G4 DQ11 (io) "Data Input/Output, Bit 10", G5 VCC (power) "Data Input/Output, Bit 2", G6 DQ13 (io) "Data Input/Output, Bit 12", G7 DQ15/A-1 (io) "3 Volt Single Power Supply", G8 NC "Ready/Busy Output (FBGA only)", H1 NC "Not connected to the die", H2 VSS (power) "Not connected to the die", H3 DQ1 (io) "Write Enable Input", H4 DQ3 (io) "Hardware Reset Pin Input", H5 DQ4 (io) "Address Input, Bit 0", H6 DQ6 (io) "Data Input/Output, Bit 5", H7 VSS (power) "Not connected to the die", H8 NC "Not connected to the die"

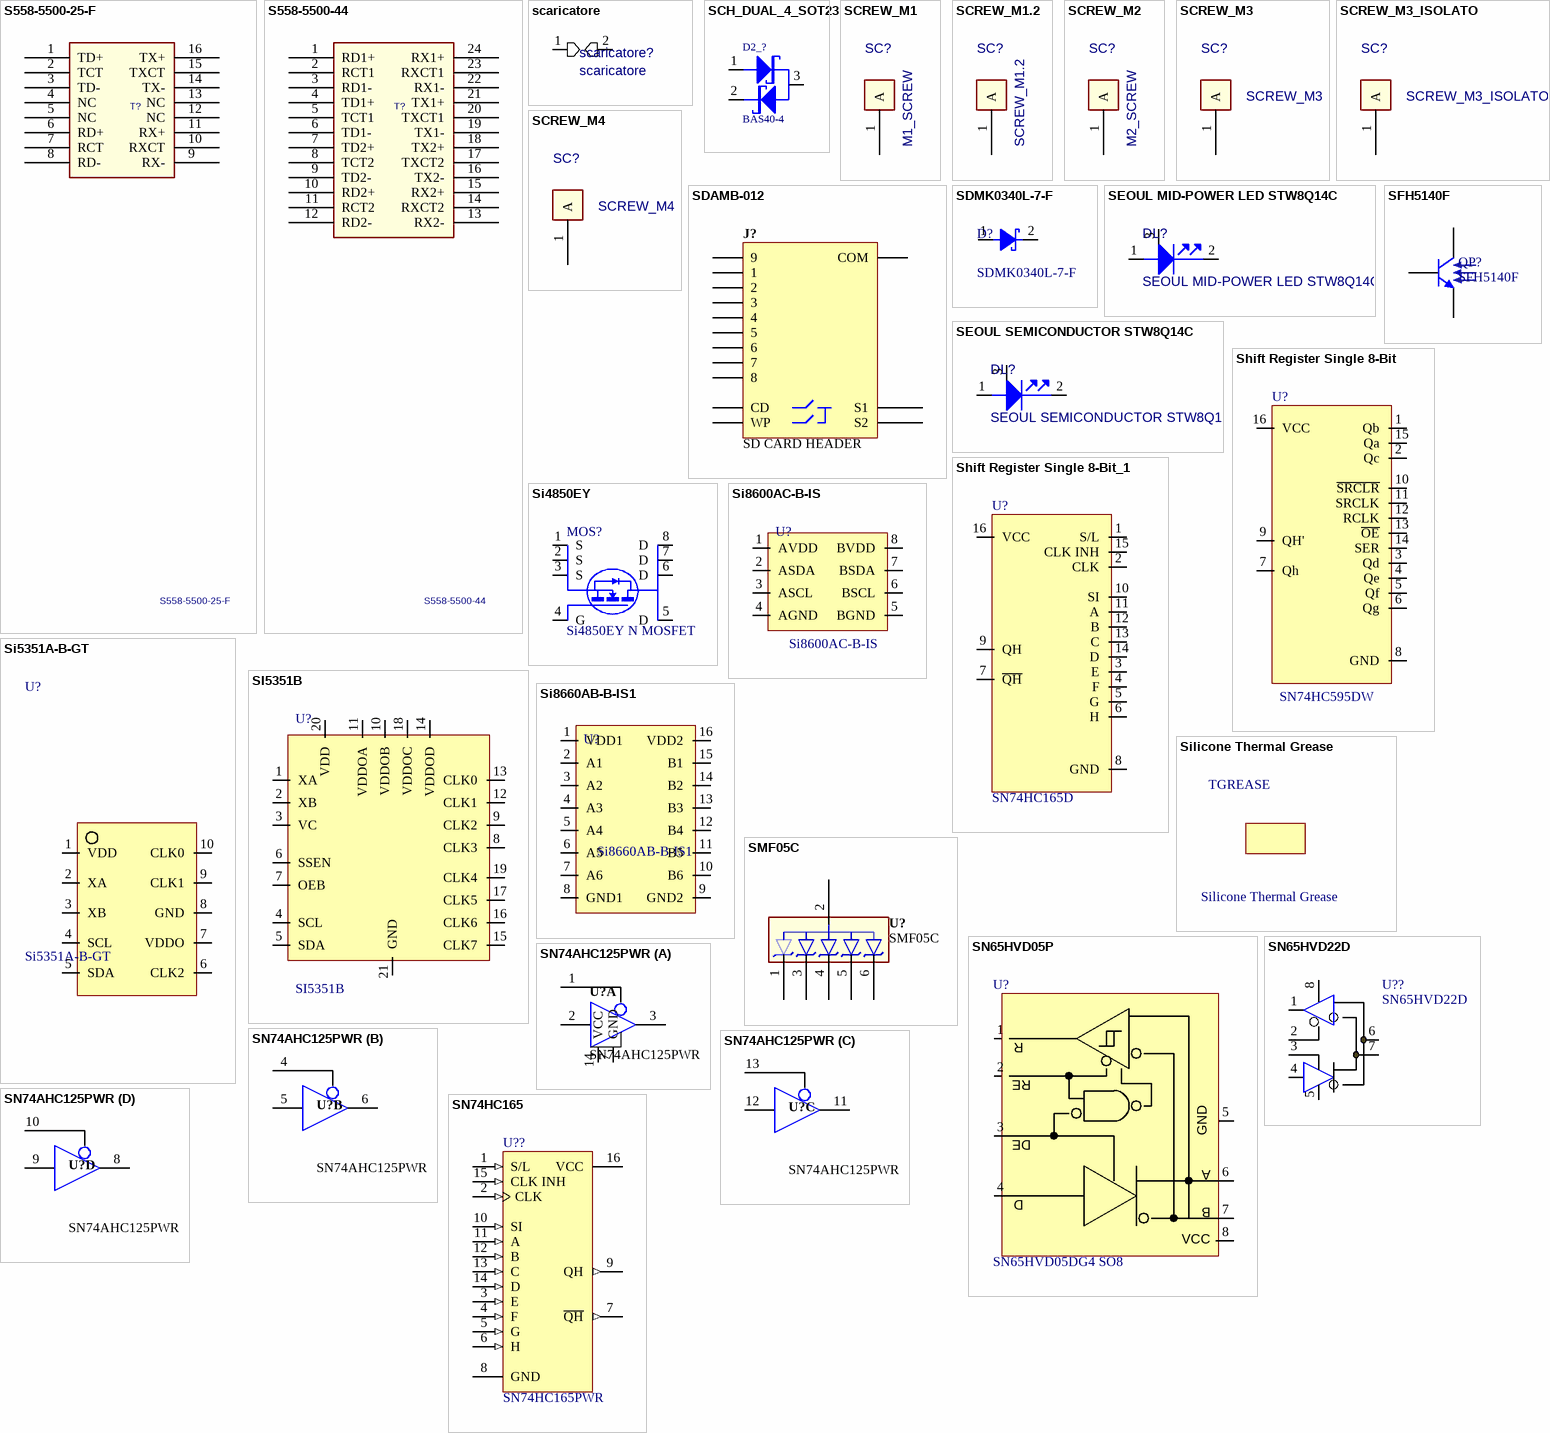
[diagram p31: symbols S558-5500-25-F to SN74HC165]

## S558-5500-25-F
designator T?
Aggiornato: NO; Costo: 0
pins: 1 TD+, 2 TCT, 3 TD-, 4 NC, 5 NC, 6 RD+, 7 RCT, 8 RD-, 9 RX-, 10 RXCT, 11 RX+, 12 NC, 13 NC, 14 TX-, 15 TXCT, 16 TX+

## S558-5500-44
designator T?
Aggiornato: NO; Costo: 0
pins: 1 RD1+, 2 RCT1, 3 RD1-, 4 TD1+, 5 TCT1, 6 TD1-, 7 TD2+, 8 TCT2, 9 TD2-, 10 RD2+, 11 RCT2, 12 RD2-, 13 RX2-, 14 RXCT2, 15 RX2+, 16 TX2-, 17 TXCT2, 18 TX2+, 19 TX1-, 20 TXCT1, 21 TX1+, 22 RX1-, 23 RXCT1, 24 RX1+

## scaricatore
designator scaricatore?  (no BOM)
Costo: 0; Aggiornato: S
footprint scaricatore
pins: 1, 2

## SCH_DUAL_4_SOT23
designator D2_?, comment BAS40-4
Part Field 1: Diodes Inc. BAS40-04-7; Aggiornato: NO; Costo: 0
footprint SOT23-3N (SOT23, 3-Leads, Body 2.9x1.3mm, Pitch 0.95mm, Lead Span 2.5mm, IPC Medium Density)
pins: 1, 2 NC, 3

## SCREW_M1
designator SC?, comment M1_SCREW  (no BOM)
Aggiornato: NO; Costo: 0
footprint SCREW_M1 (Footprint not found)
footprint SCREW_M2_TORR4.6
pins: 1 A

## SCREW_M1.2
designator SC?  (no BOM)
Aggiornato: NO; Costo: 0
footprint SCREW_M1.2 (Footprint not found)
footprint SCREW_M2_TORR4.6
pins: 1 A

## SCREW_M2
designator SC?, comment M2_SCREW  (no BOM)
Aggiornato: NO; Costo: 0
footprint SCREW_M2
footprint SCREW_M2_TORR4.6
pins: 1 A

## SCREW_M3
designator SC?  (no BOM)
Costo: 0; Aggiornato: NO
footprint SCREW_M3_ELECTRIC
pins: 1 A

## SCREW_M3_ISOLATO
designator SC?  (no BOM)
Costo: 0; Aggiornato: NO
footprint SCREW_M3
pins: 1 A

## SCREW_M4
designator SC?  (no BOM)
Costo: 0; Aggiornato: NO
footprint SCREW M4
pins: 1 A

## SDAMB-012
designator J?, comment SD CARD HEADER
SD Card Connector, Type A without Cover; Surface Mount; 9-Position; Max Current: mA; Aggiornato: NO; Costo: 0
footprint SDAMB-012
pins: 1, 2, 3, 4, 5, 6, 7, 8, 9, CD, COM, S1, S2, WP

## SDMK0340L-7-F
designator D?
Diodo Diodes Inc, Montaggio superficiale, 30mA, 40V, SOD-323; Costo: 0,064; Aggiornato: S; ContoLavoro: 0
footprint SOD-323  SDMK0340L-7-F
pins: 1, 2

## SEOUL MID-POWER LED STW8Q14C
designator DL?
Costo: 0; Aggiornato: si; ContoLavoro: 1
footprint LED_SEOUL MIDPOWER STW8Q14C
pins: 1 ANODE, 2 CATHODE, 3 HEATER

## SEOUL SEMICONDUCTOR STW8Q14C
designator DL?
Detail: MATELICI ELNA; Aggiornato: si; ContoLavoro: 1
footprint LED_5630_SEOUL SEMICONDUCTOR STW8Q14C
pins: 1 ANODE, 2 CATHODE, 3 HEATER

## SFH5140F
designator QP?
Fotodiodo SFH5140F; Aggiornato: NO; Costo: 0,65; ContoLavoro: 0
footprint TO-92A (TO, Flat Index; 3 In-Line, Axial Leads; Body Dia. 4.5mm; Leads 0.51 x 0.48 mm (max))
simulation model 2N3904 (NPN)
signal-integrity model 2N3904
pins: 1 E, 2 B, 3 C

## Shift Register Single 8-Bit
designator U?, comment SN74HC595DW
Costo: 0,172; Aggiornato: NO; ContoLavoro: 0
footprint SO16
pins: 1 Qb, 2 Qc, 3 Qd, 4 Qe, 5 Qf, 6 Qg, 7 Qh, 8 GND, 9 QH', 10 ~{SRCLR}, 11 SRCLK, 12 RCLK, 13 ~{OE}, 14 SER, 15 Qa, 16 VCC

## Shift Register Single 8-Bit_1
designator U?, comment SN74HC165D
Costo: 0,172; Aggiornato: NO; ContoLavoro: 0
footprint SO16
pins: 1 S/L, 2 CLK, 3 E, 4 F, 5 G, 6 H, 7 ~{QH}, 8 GND, 9 QH, 10 SI, 11 A, 12 B, 13 C, 14 D, 15 CLK INH, 16 VCC

## Si4850EY
designator MOS?, comment Si4850EY N MOSFET
NMOS_DEPLETION SOIC8; Detail: prezzo RS<50pz; Costo: 1,196; Aggiornato: SI; ContoLavoro: 0
footprint SOIC150-8N-COPPER-SPREAD (SOIC, 8-Leads, Body 4.9x3.9mm, Pitch 1.27mm, IPC Medium Density)
pins: 1 S, 2 S, 3 S, 4 G, 5 D, 6 D, 7 D, 8 D
2 alternate drawings of the same symbol

## Si5351A-B-GT
designator U?
Si5351A-B-GTPROGRAMMABLE CLOCK GENERATOR; Aggiornato: s; Costo: 0,84; ContoLavoro: 1
footprint MSOP_10 (Footprint not found)
pins: 1 VDD, 2 XA, 3 XB, 4 SCL, 5 SDA, 6 CLK2, 7 VDDO, 8 GND, 9 CLK1, 10 CLK0

## SI5351B
designator U?
SI5351B PROGRAMMABLE CLOCK GENERATOR; HPcode: ICSI5351B; Aggiornato: s; Costo: 2,2; ContoLavoro: 1
footprint QFN-ML20_M (Footprint not found)
pins: 1 XA, 2 XB, 3 VC, 4 SCL, 5 SDA, 6 SSEN, 7 OEB, 8 CLK3, 9 CLK2, 10 VDDOB, 11 VDDOA, 12 CLK1, 13 CLK0, 14 VDDOD, 15 CLK7, 16 CLK6, 17 CLK5, 18 VDDOC, 19 CLK4, 20 VDD, 21 GND

## Si8600AC-B-IS
designator U?
Si8600 2 channels bidirectional digital isolator; Aggiornato: s; Costo: 2,85; ContoLavoro: 1
footprint SOIC8
pins: 1 AVDD, 2 ASDA, 3 ASCL, 4 AGND, 5 BGND, 6 BSCL, 7 BSDA, 8 BVDD

## Si8660AB-B-IS1
designator U?
Si8660 6 channels digital isolator; Aggiornato: s; Costo: 1,874; ContoLavoro: 1
footprint SOIC16
pins: 1 VDD1, 2 A1, 3 A2, 4 A3, 5 A4, 6 A5, 7 A6, 8 GND1, 9 GND2, 10 B6, 11 B5, 12 B4, 13 B3, 14 B2, 15 B1, 16 VDD2

## Silicone Thermal Grease
designator TGREASE  (mechanical)
Aggiornato: NO; Costo: 0

## SMF05C
designator U?
TVS Diode Array  For ESD and Latch-Up Protection; Junction Capacitance: 130 pF; Peak Pulse Current: 8 A; Peak Pulse Power: 100 W; Reverse Breakdown Voltage: 6 V; Aggiornato: NO; Costo: 0
footprint SC70_6L
pins: 1, 2, 3, 4, 5, 6

## SN65HVD05P
designator U?, comment SN65HVD05DG4 SO8
Costo: 3,77; Aggiornato: NO; ContoLavoro: 0
footprint SO8
pins: 1, 2, 3, 4, 5, 6, 7, 8

## SN65HVD22D
designator U??
SN65HVD22D SOIC-8 Extended_Common-Mode_RS-485_Transceiver_4.5V_-40°C+85°C SMD; Aggiornato: NO; Costo: 0
3D model SO8_0_0000 (PCB3D Model)
footprint SO8_texas (Small Outline; 8 Leads; Body (LxW)  5.0mm x 4.0mm Pitch 1.27 mm)
pins: 1 R, 2 R~{E}, 3 DE, 4 D, 5 -VCC (power), 6 A, 7 B (power), 8 VCC+
1 alternate drawing of the same symbol

## SN74AHC125PWR
designator U?
SN74AHC125PWR quad buffer; Aggiornato: SI; Costo: 0,29; ContoLavoro: 0
footprint TSSOP14
part A pins: 1 A0, 2 B0, 3 Q0, 7 GND, 14 VCC
part B pins: 4 A1, 5 B1, 6 Q1
part C pins: 11 Q2, 12 B2, 13 A2
part D pins: 8 Q3, 9 B3, 10 A3

## SN74HC165
designator U??, comment SN74HC165PWR
Part Field 1: TI SN74HC165PWR; Description1: SN74HC165PWR TSSOP16 8_BIT_PARALLEL_LOAD_SHIFT_REGISTERS SMD; Aggiornato: NO; Costo: 0
signal-integrity model SN74HC165D
footprint TSSOP640-16N (SOP, 16-Leads, Body 5x4.4mm, Pitch 0.65mm, IPC Medium Density)
pins: 1 S/L (in), 2 CLK (in), 3 E (in), 4 F (in), 5 G (in), 6 H (in), 7 ~{QH} (out), 8 GND (power), 9 QH (out), 10 SI (in), 11 A (in), 12 B (in), 13 C (in), 14 D (in), 15 CLK INH (in), 16 VCC (power)

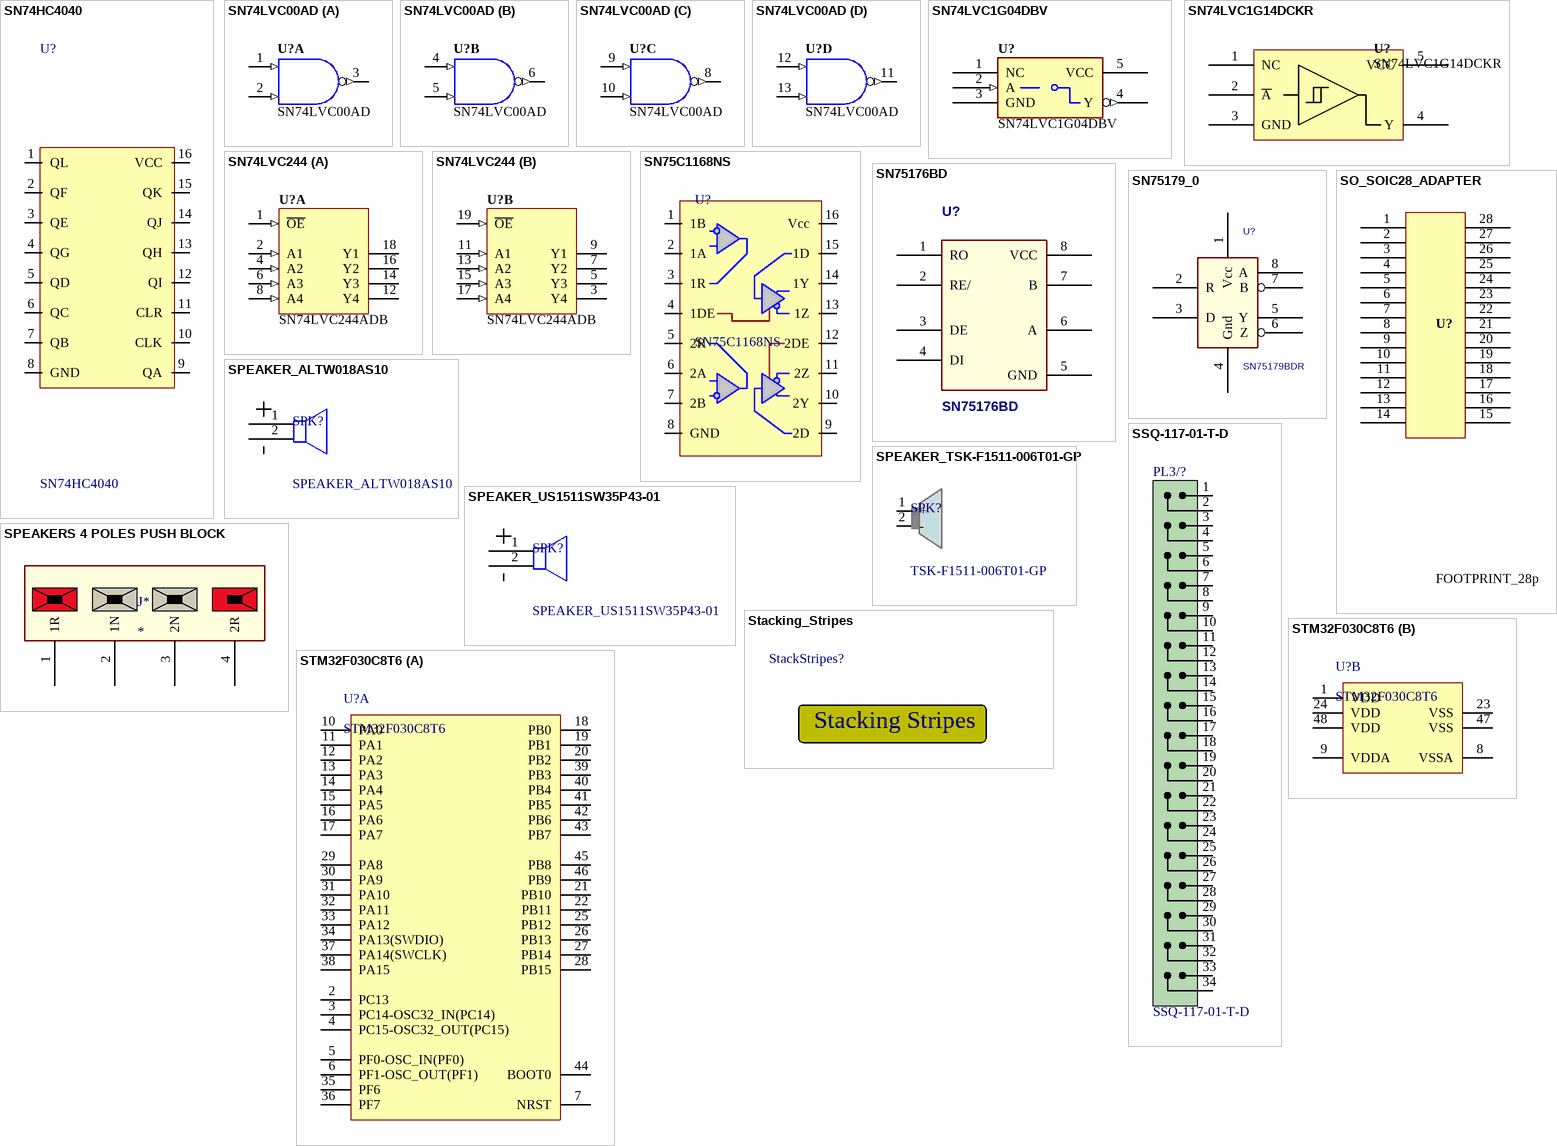
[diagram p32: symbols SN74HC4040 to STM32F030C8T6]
